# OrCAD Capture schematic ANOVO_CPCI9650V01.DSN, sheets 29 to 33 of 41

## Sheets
29 -J4 USB &SATA &AUDIO &COM: size C; title: 29--J4 HDD&LVDS&AUDIO
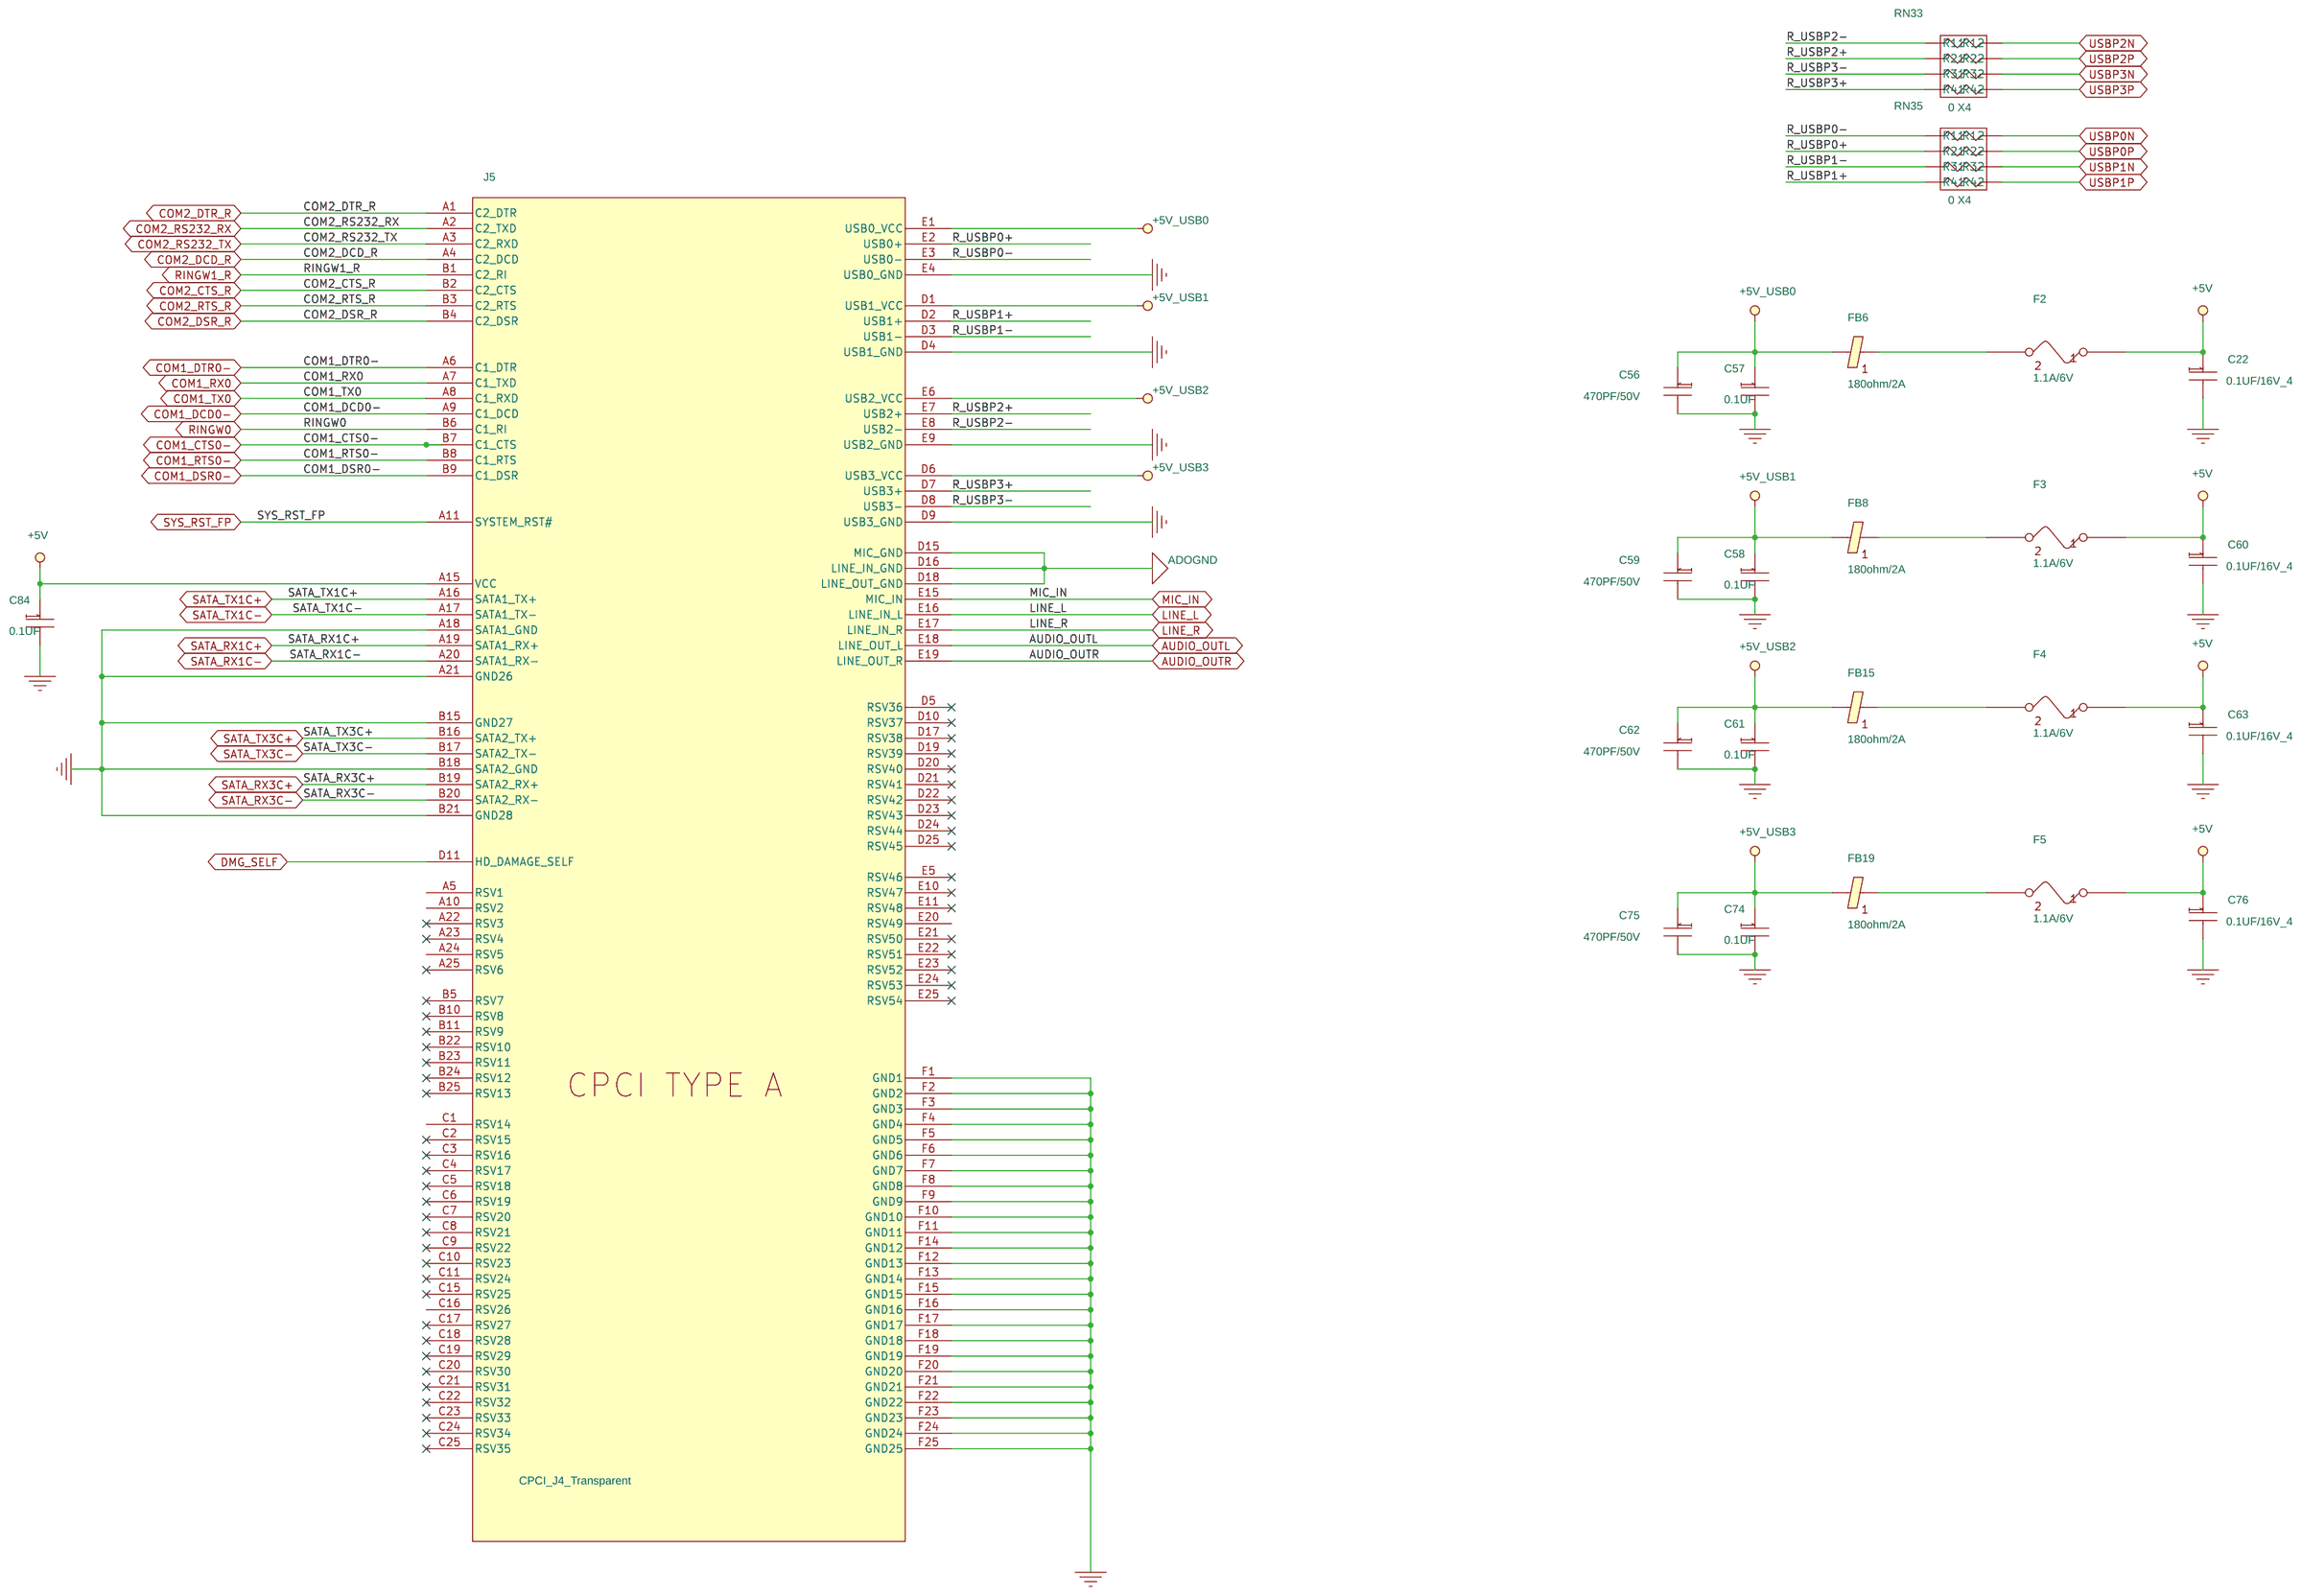
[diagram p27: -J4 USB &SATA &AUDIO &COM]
30 -J5 VGA &DVI &LVDS: size C; title: 30--J5 VGA&USB&ETC
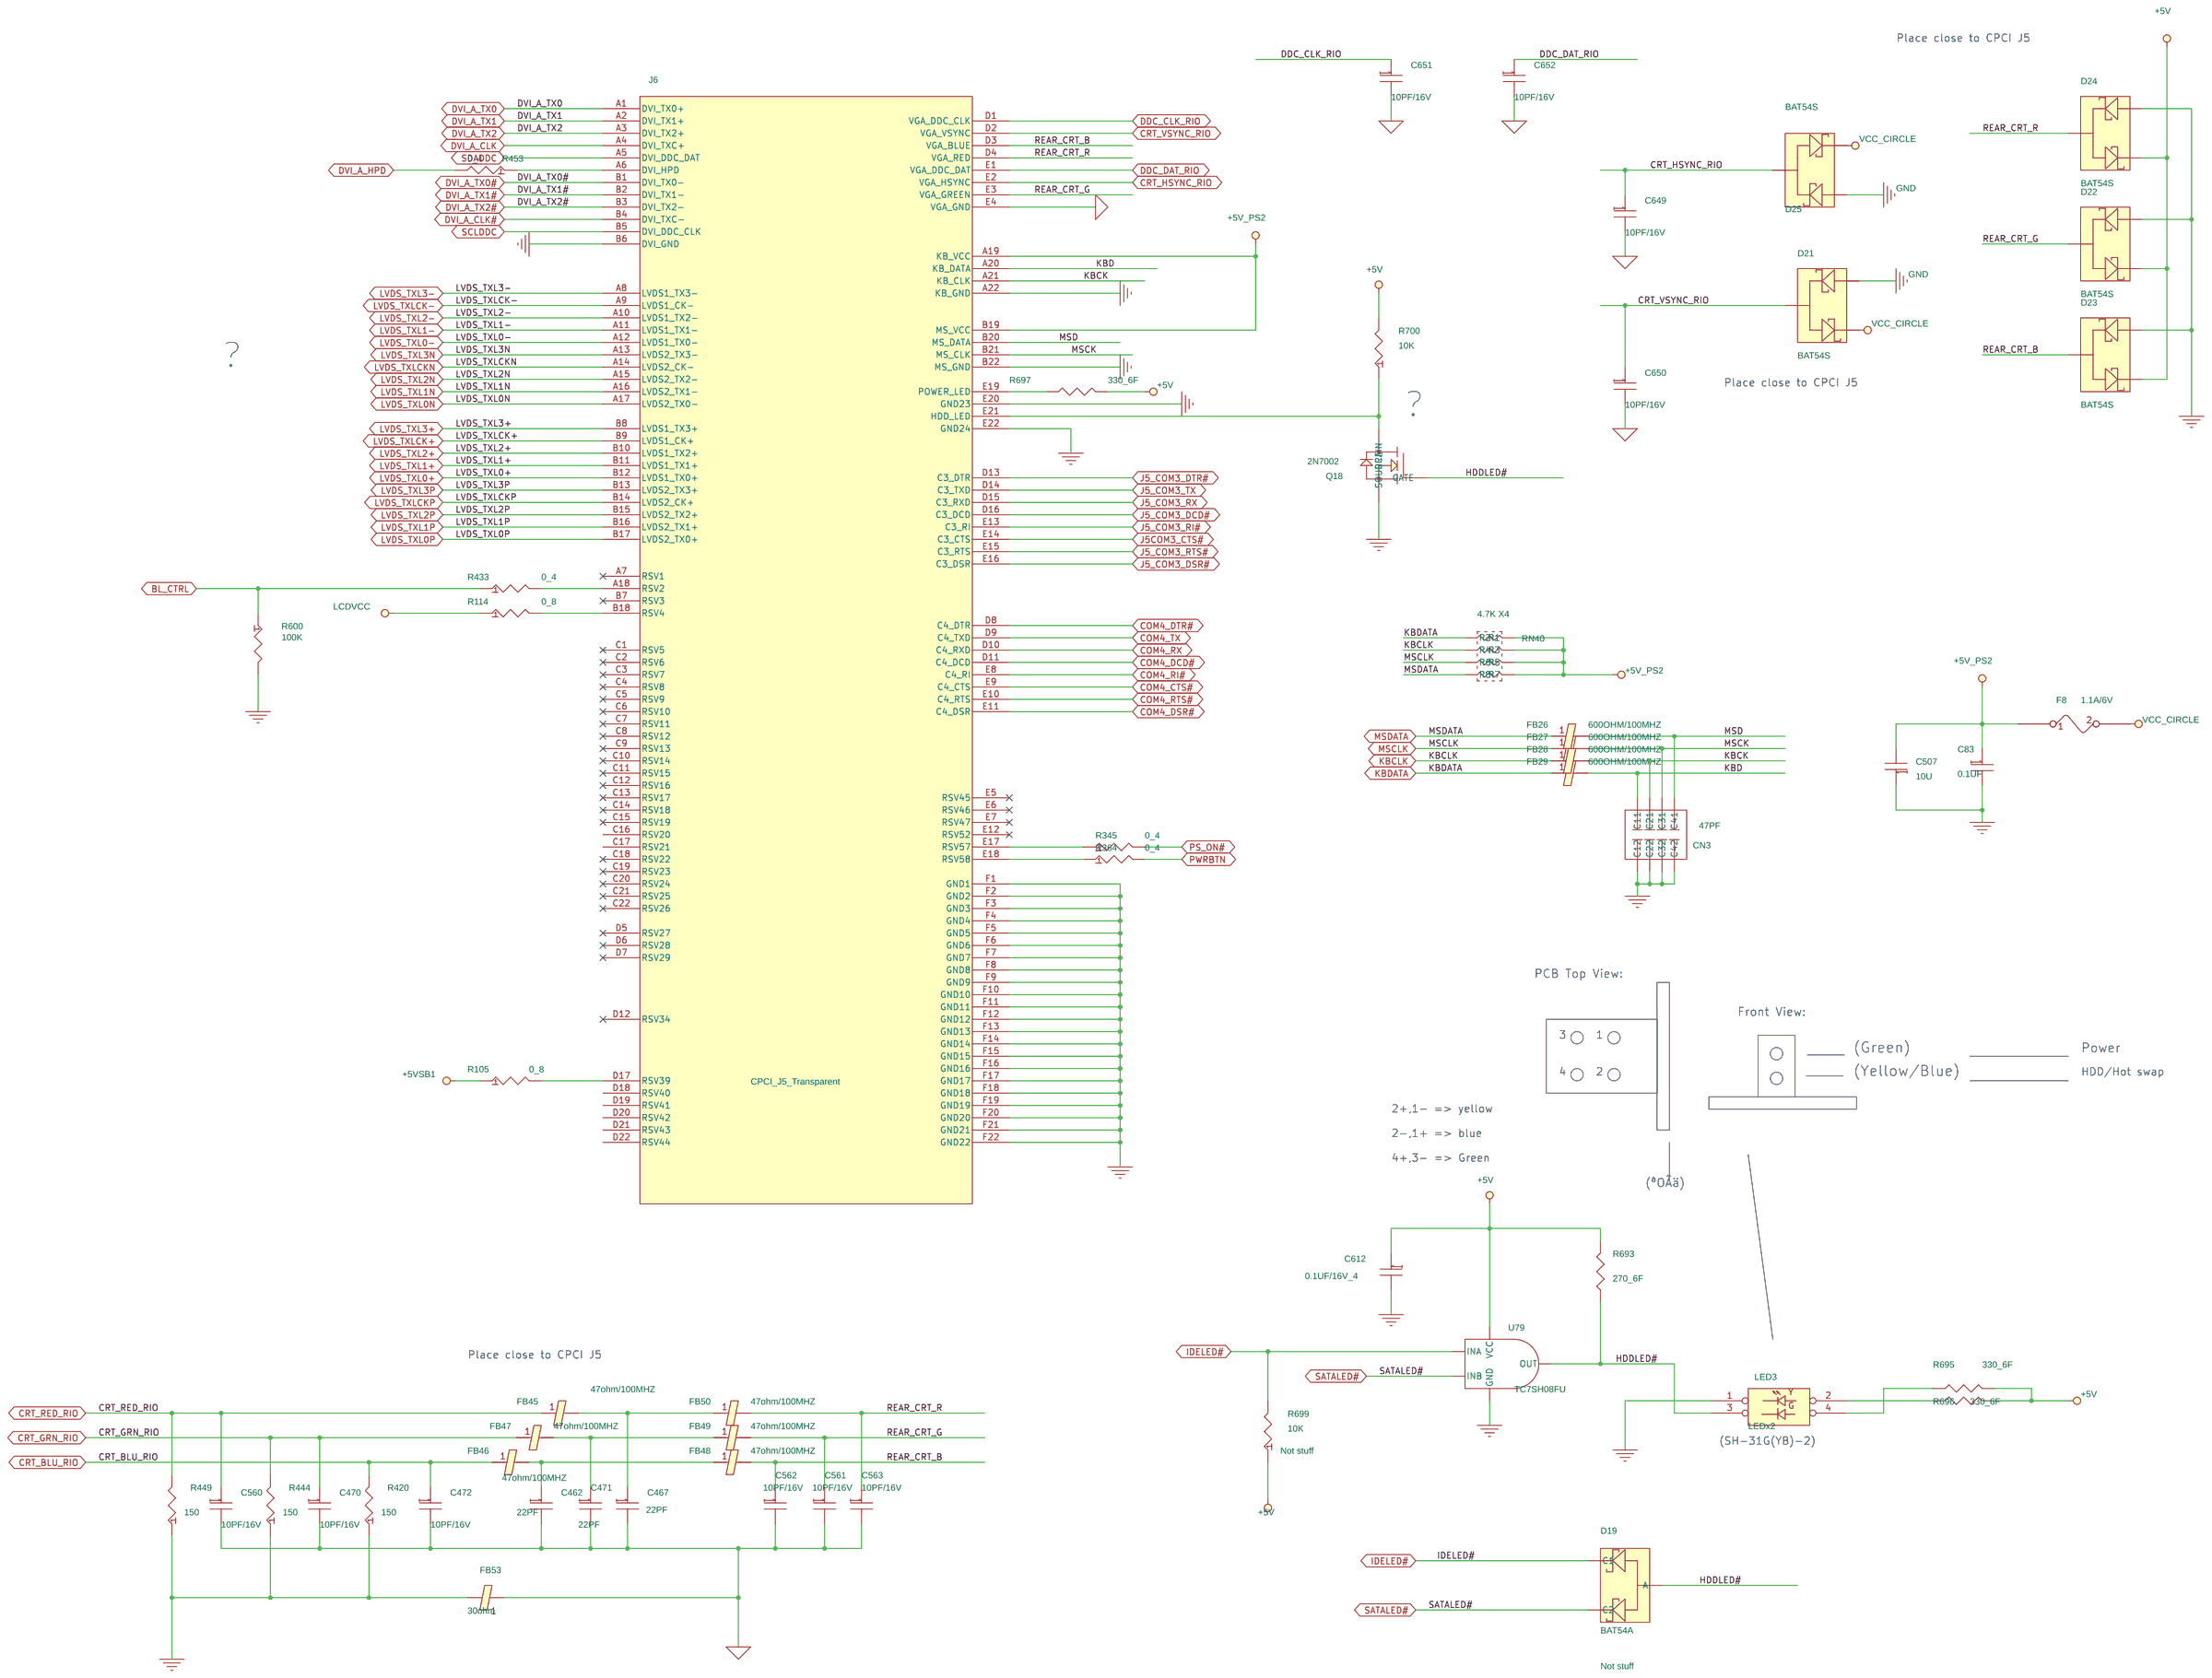
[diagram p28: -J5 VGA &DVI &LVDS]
31 -VCORE: size C; title: 31--POWER-ISL6262(VCORE)
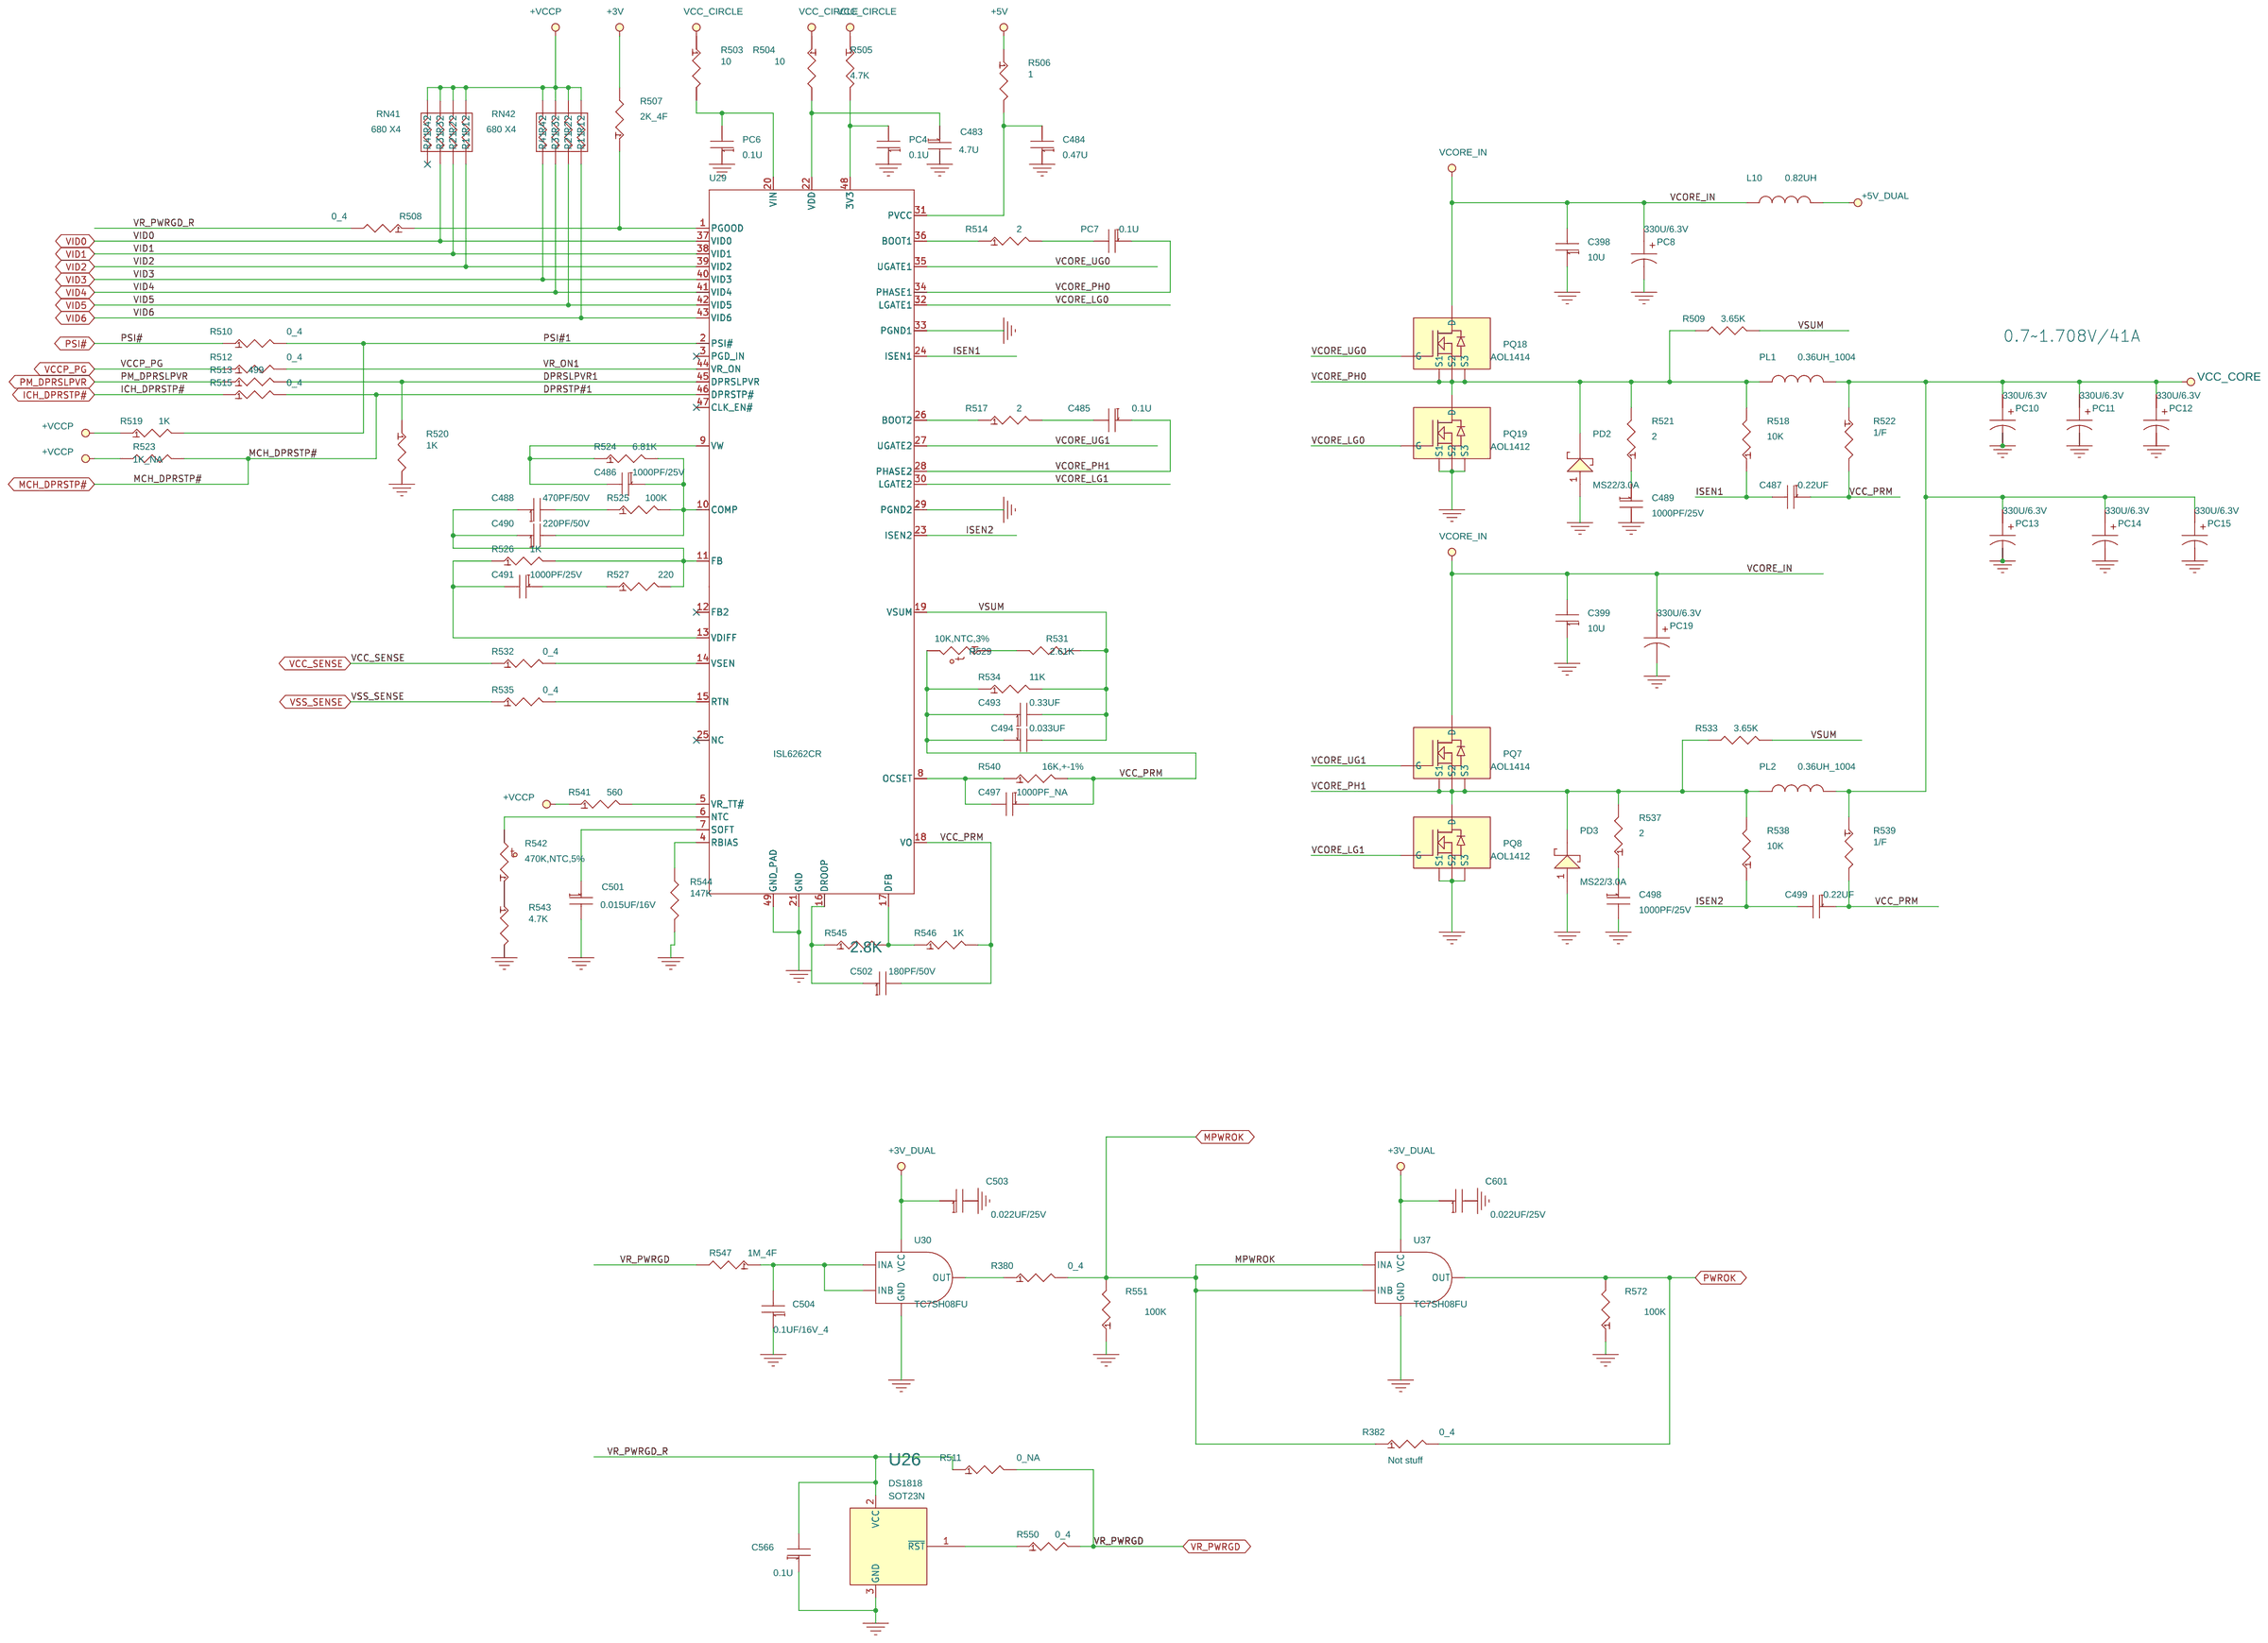
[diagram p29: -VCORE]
32 -1.05V & 1.25V: size C; title: 32--ISL6227(MCH&ICH)
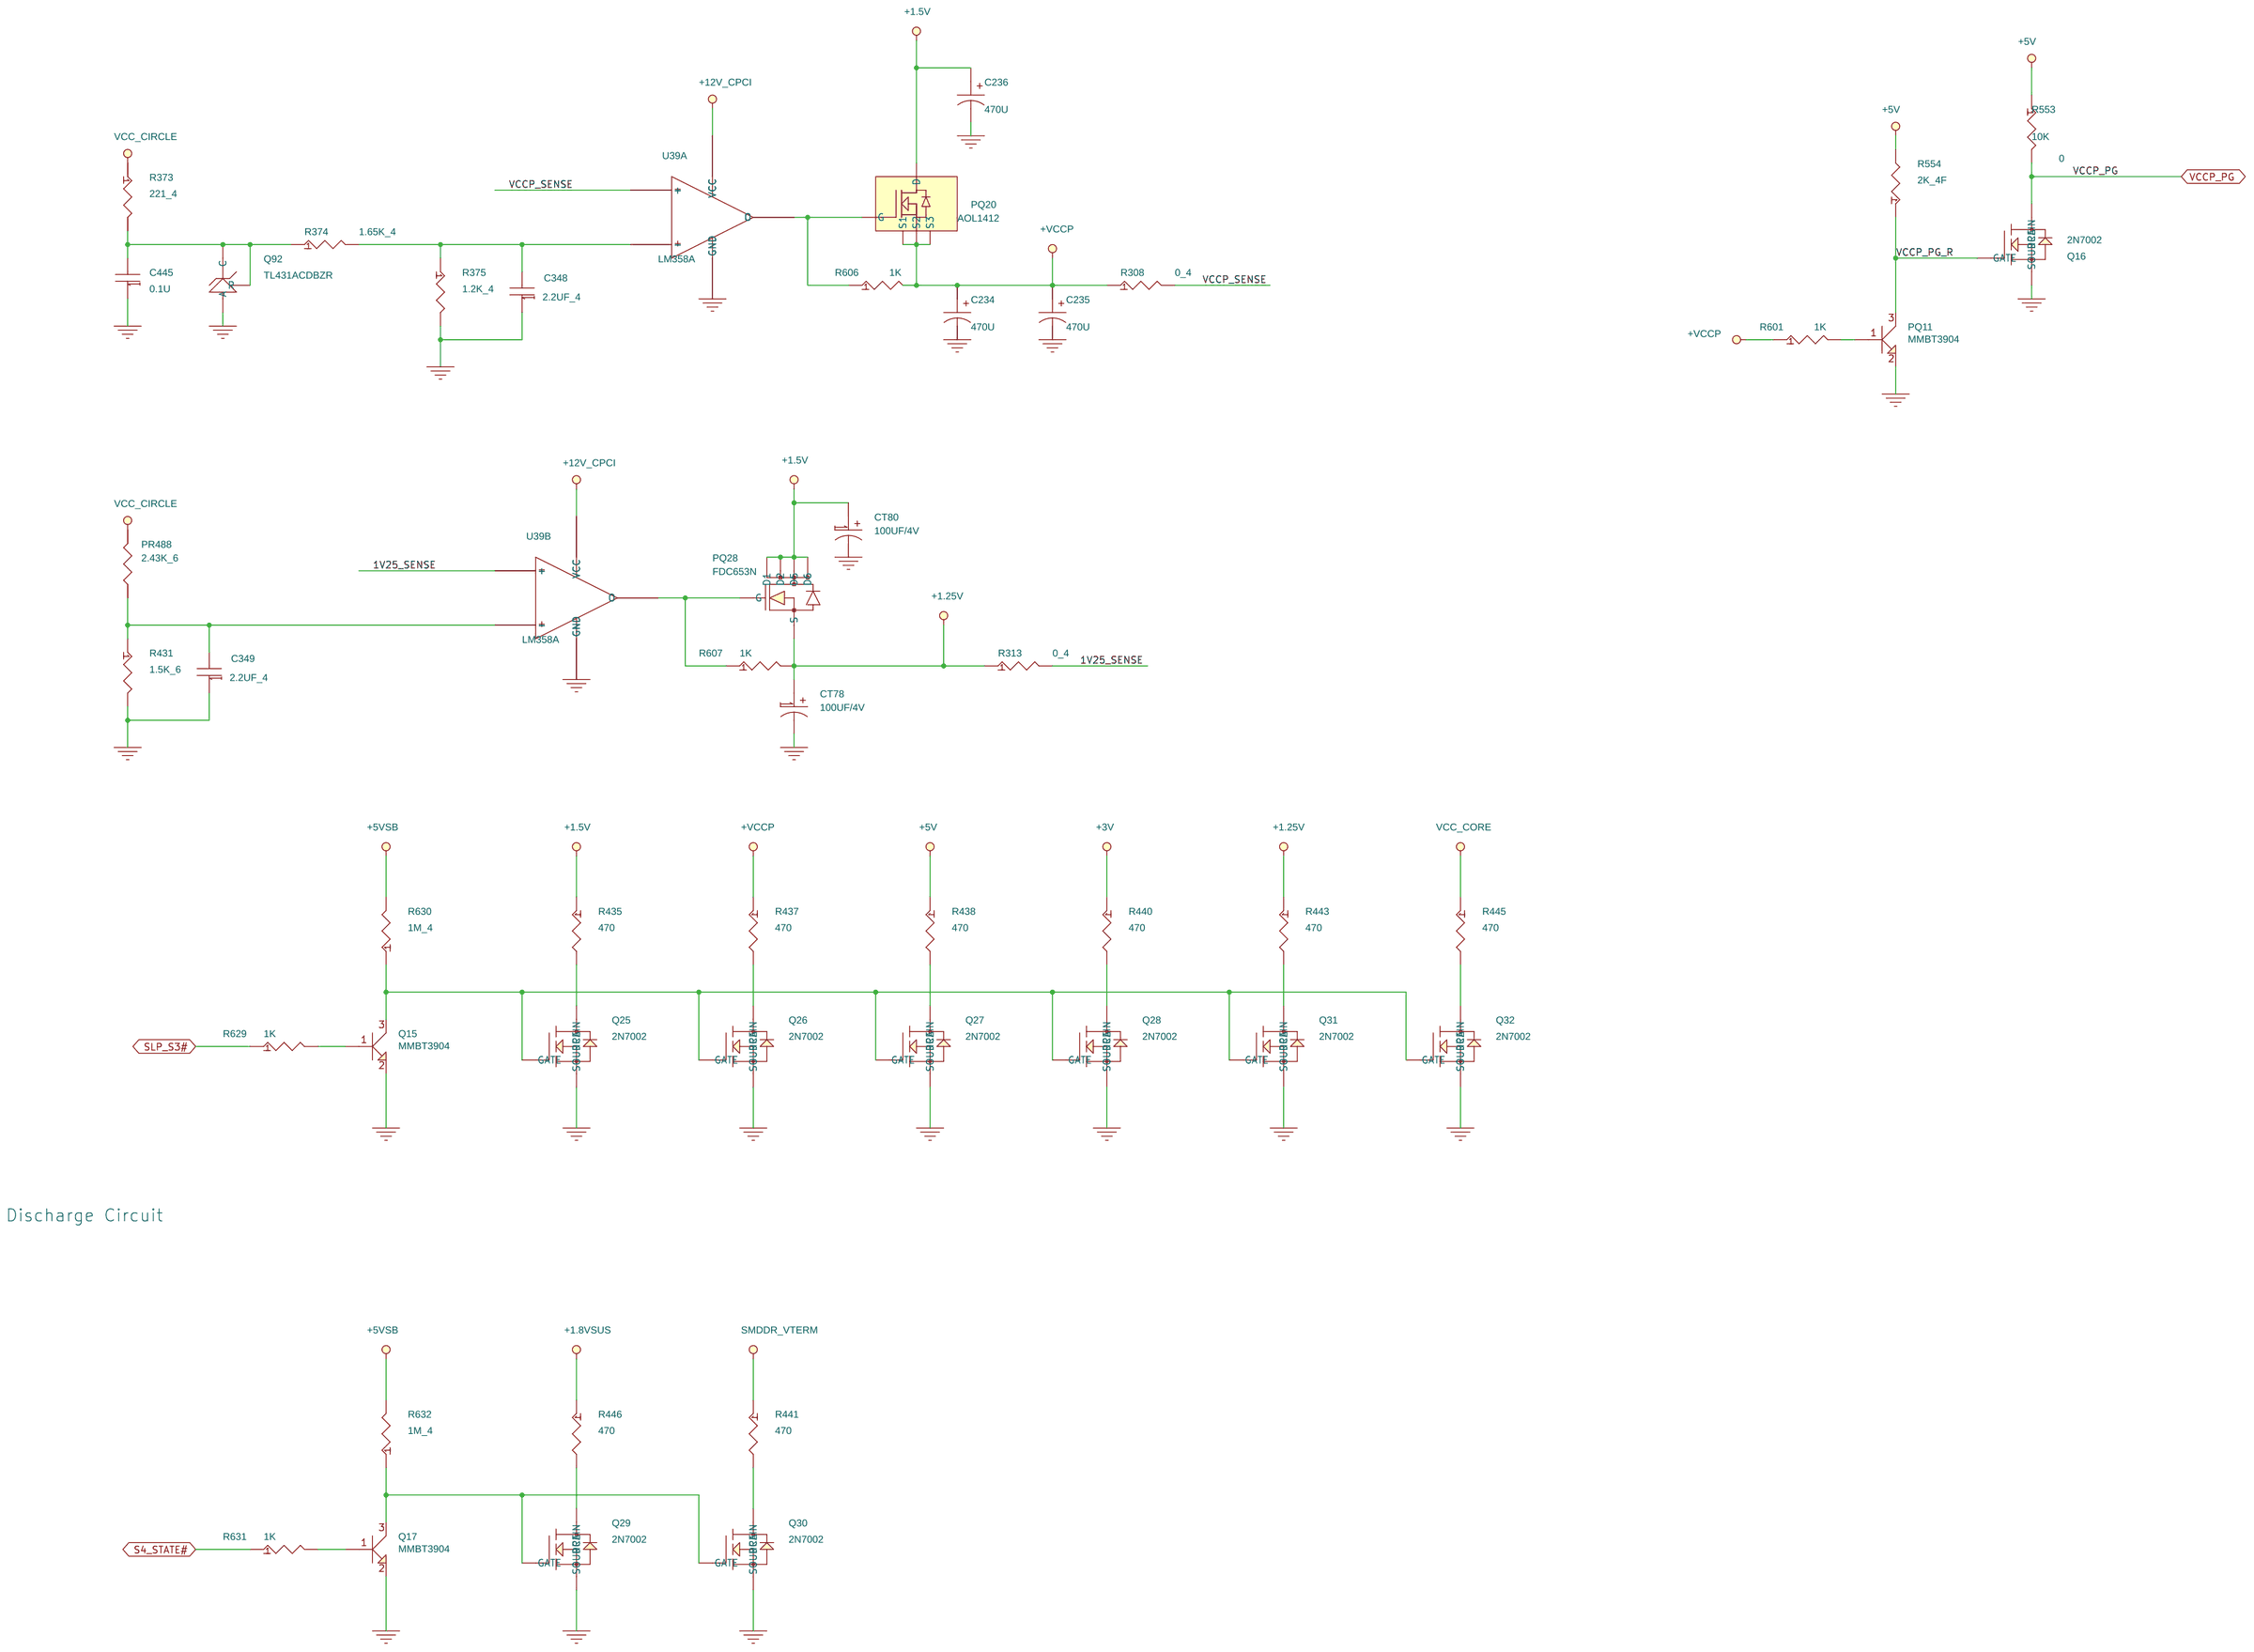
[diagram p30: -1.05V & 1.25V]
33 -1.8V & 1.5V: size C; title: 33--1.8VSUS/0.9VTERM(TPS51116)
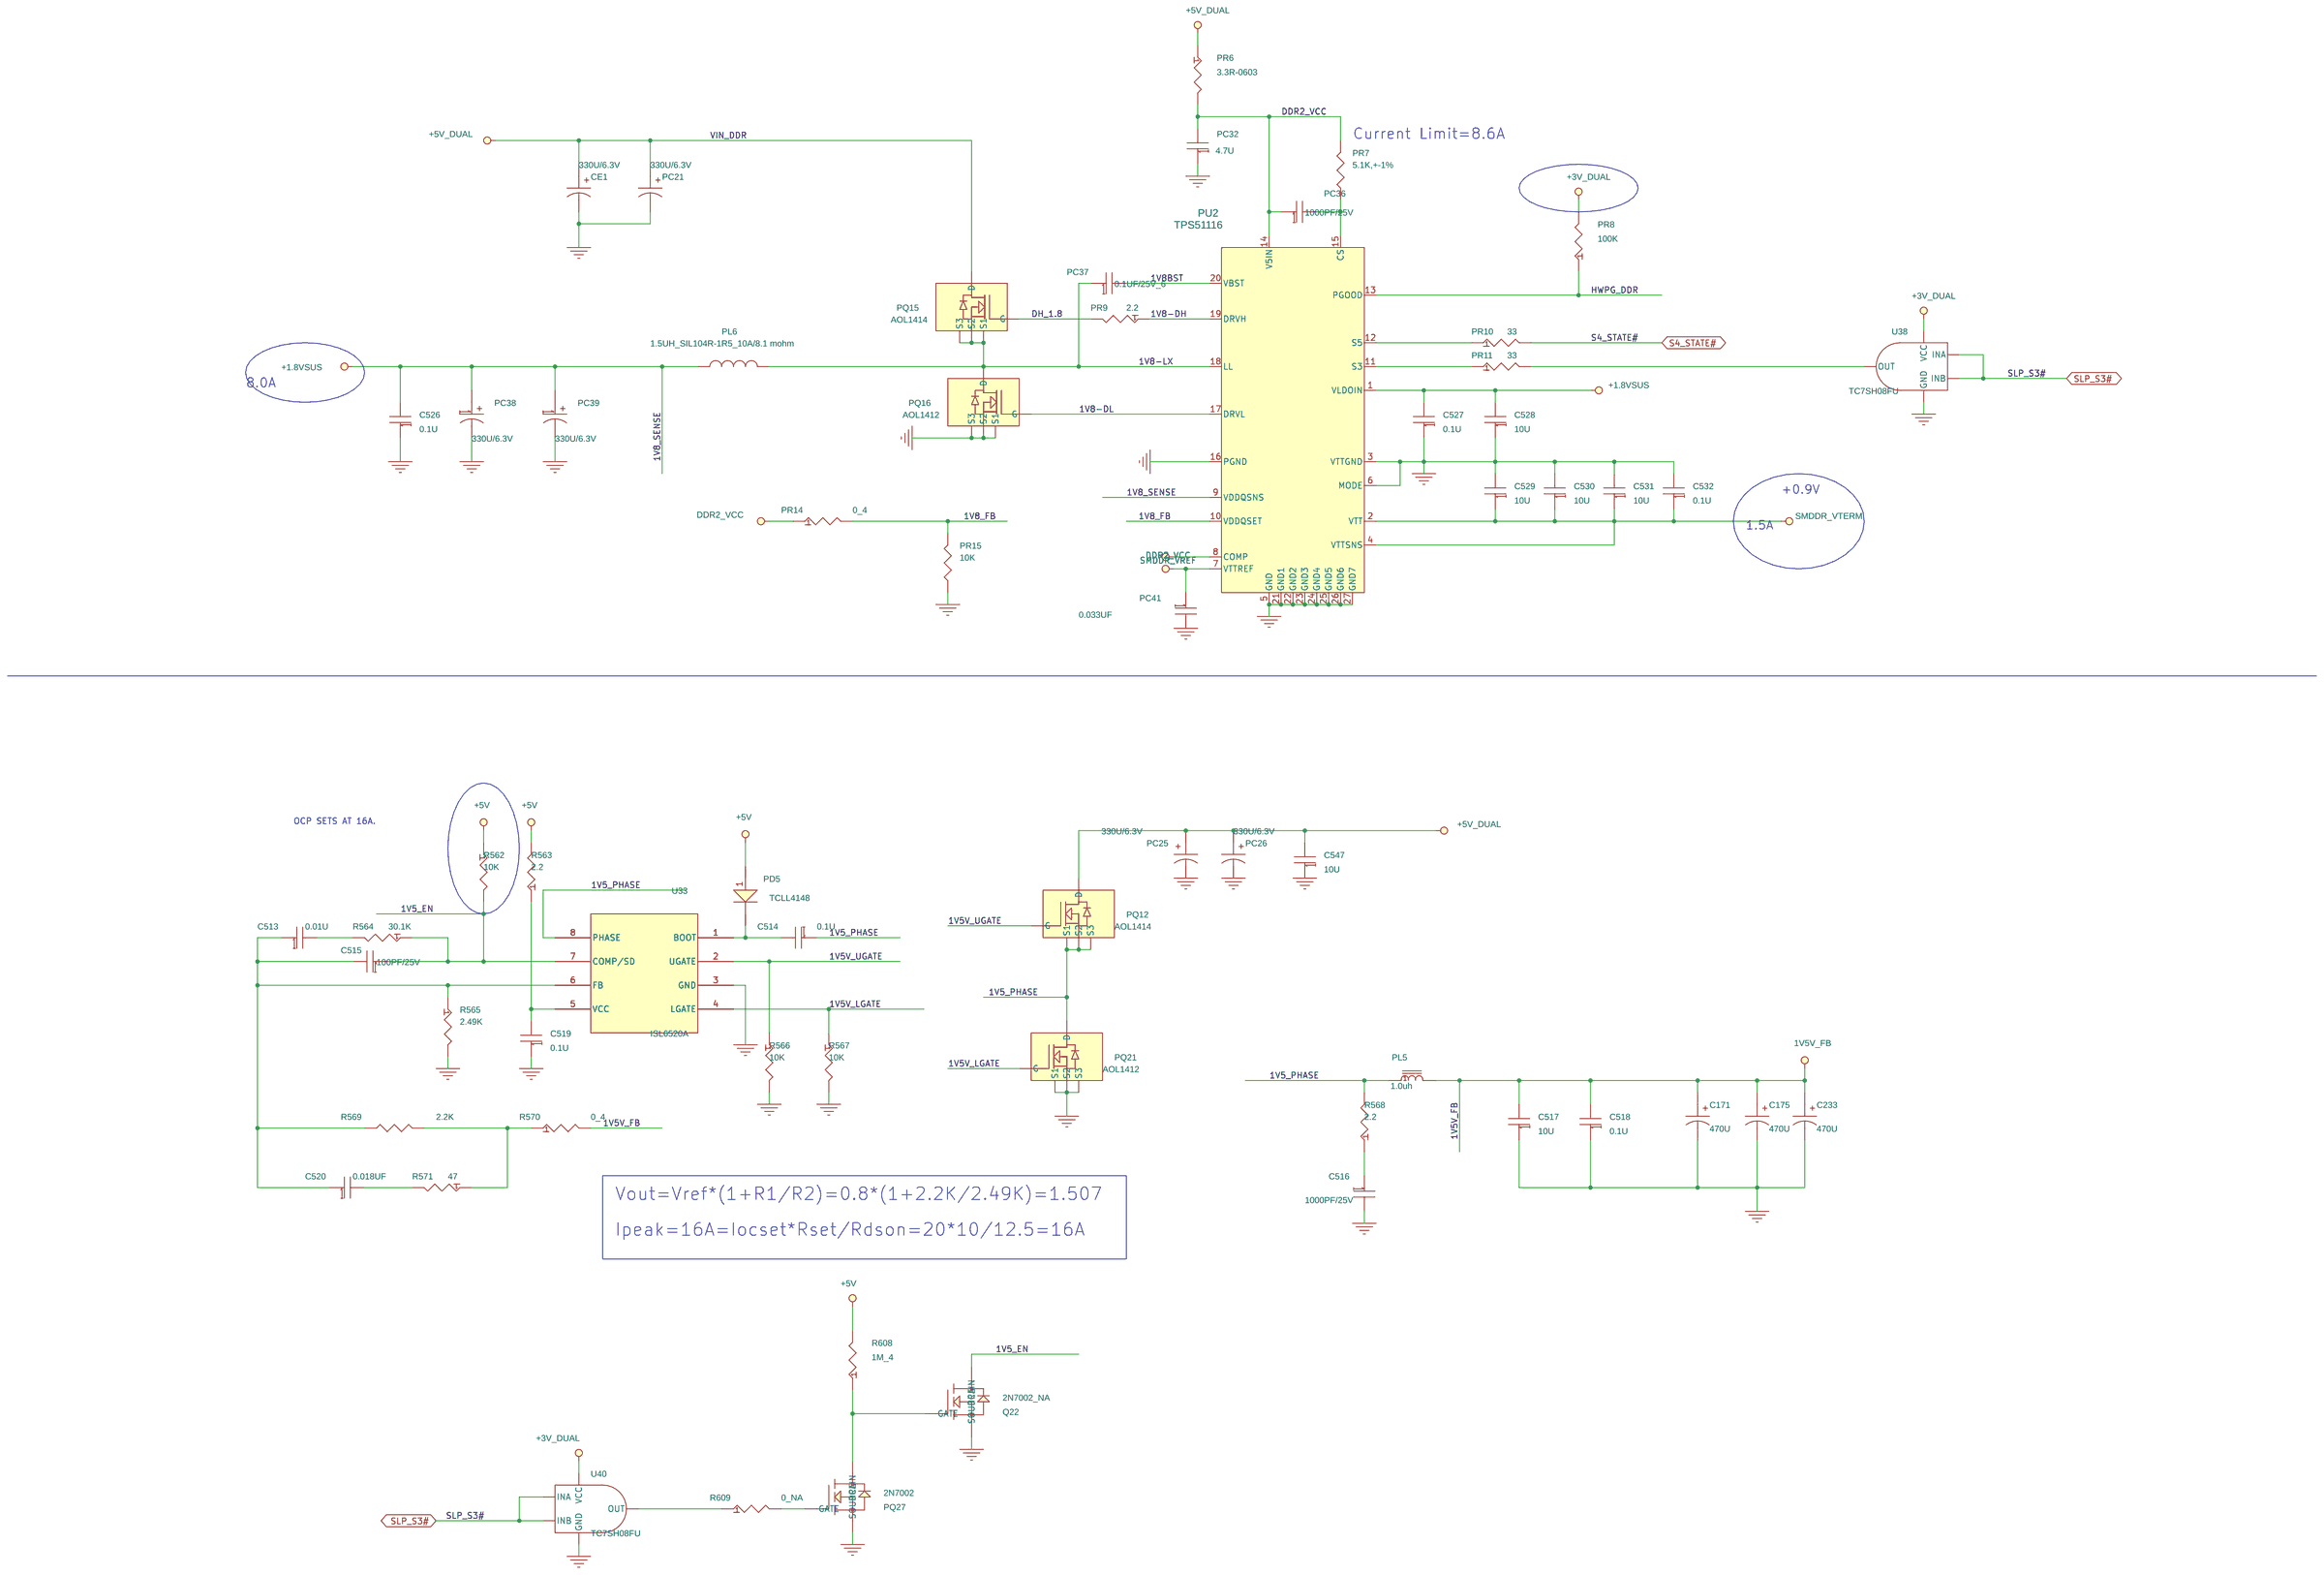
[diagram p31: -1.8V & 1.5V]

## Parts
sheet -1.05V & 1.25V
C234  470U  [1812A]
C235  470U  [1812A]
C236  470U  [1812A]
C348  2.2UF_4  [0402D]
C349  2.2UF_4  [0402D]
C445  0.1U  [0402D]
CT78  100UF/4V  [C3530]
CT80  100UF/4V  [C3530]
PQ11  MMBT3904  [SOT23N_5]
PQ20  AOL1412  [SO_8FL_5P_OA]
PQ28  FDC653N  [SSOT6-2_8-95]
PR488  2.43K_6  [0603D]
Q15  MMBT3904  [SOT23N_5]
Q16  2N7002  [SOT23N_5]
Q17  MMBT3904  [SOT23N_5]
Q25  2N7002  [SOT23N_5]
Q26  2N7002  [SOT23N_5]
Q27  2N7002  [SOT23N_5]
Q28  2N7002  [SOT23N_5]
Q29  2N7002  [SOT23N_5]
Q30  2N7002  [SOT23N_5]
Q31  2N7002  [SOT23N_5]
Q32  2N7002  [SOT23N_5]
Q92  TL431ACDBZR  [SOT23N]
R308  0_4  [0402D]
R313  0_4  [0402D]
R373  221_4  [0402D]
R374  1.65K_4  [0402D]
R375  1.2K_4  [0402D]
R431  1.5K_6  [0402D]
R435  470  [0402D]
R437  470  [0402D]
R438  470  [0402D]
R440  470  [0402D]
R441  470  [0402D]
R443  470  [0402D]
R445  470  [0402D]
R446  470  [0402D]
R553  10K  [0402D]
R554  2K_4F  [0402D]
R601  1K  [0402D]
R606  1K  [0402D]
R607  1K  [0402D]
R629  1K  [0402D]
R630  1M_4  [0402D]
R631  1K  [0402D]
R632  1M_4  [0402D]
U39  LM358A  [SO8]  (sections A,B)
sheet -1.8V & 1.5V
C171  470U  [1812A]
C175  470U  [1812A]
C233  470U  [1812A]
C513  0.01U  [0402D]
C514  0.1U  [0402D]
C515  100PF/25V  [0603D]
C516  1000PF/25V  [0603D]
C517  10U  [0805D]
C518  0.1U  [0402D]
C519  0.1U  [0402D]
C520  0.018UF  [0603D]
C526  0.1U  [0402D]
C527  0.1U  [0402D]
C528  10U  [0805D]
C529  10U  [0805D]
C530  10U  [0805D]
C531  10U  [0805D]
C532  0.1U  [0402D]
C547  10U  [0805D]
CE1  330U/6.3V  [1812A]
PC21  330U/6.3V  [1812A]
PC25  330U/6.3V  [1812A]
PC26  330U/6.3V  [1812A]
PC32  4.7U  [0805D]
PC36  1000PF/25V  [0603D]
PC37  0.1UF/25V_6  [0603D]
PC38  330U/6.3V  [1812A]
PC39  330U/6.3V  [1812A]
PC41  0.033UF  [0603D]
PD5  TCLL4148  [DC1506N]
PL5  1.0uh  [smpi1004]
PL6  1.5UH_SIL104R-1R5_10A/8.1 mohm  [CDRH104R]
PQ12  AOL1414  [SO_8FL_5P_OA]
PQ15  AOL1414  [SO_8FL_5P_OA]
PQ16  AOL1412  [SO_8FL_5P_OA]
PQ21  AOL1412  [SO_8FL_5P_OA]
PQ27  2N7002  [SOT23N_5]
PR6  3.3R-0603  [0603D]
PR7  5.1K,+-1%  [0402D]
PR8  100K  [0402D]
PR9  2.2  [0805D]
PR10  33  [0402D]
PR11  33  [0402D]
PR14  0_4  [0402D]
PR15  10K  [0402D]
PU2  TPS51116  [TSSOP20-6_4-65-27P]
Q22  2N7002_NA  [SOT23N_5]
R562  10K  [0402D]
R563  2.2  [0805D]
R564  30.1K  [0603D]
R565  2.49K  [0603D]
R566  10K  [0402D]
R567  10K  [0402D]
R568  2.2  [0805D]
R569  2.2K  [0603D]
R570  0_4  [0402D]
R571  47  [0603D]
R608  1M_4  [0402D]
R609  0_NA  [0402D]
U33  ISL6520A  [SO8]
U38  TC7SH08FU  [SSOP5_TOSHIBA]
U40  TC7SH08FU  [SSOP5_TOSHIBA]
sheet -J4 USB &SATA &AUDIO &COM
C22  0.1UF/16V_4  [0402D]
C56  470PF/50V  [0402D]
C57  0.1UF  [0402D]
C58  0.1UF  [0402D]
C59  470PF/50V  [0402D]
C60  0.1UF/16V_4  [0402D]
C61  0.1UF  [0402D]
C62  470PF/50V  [0402D]
C63  0.1UF/16V_4  [0402D]
C74  0.1UF  [0402D]
C75  470PF/50V  [0402D]
C76  0.1UF/16V_4  [0402D]
C84  0.1UF  [0402D]
F2  1.1A/6V  [POLYSW_MINISMDC110]
F3  1.1A/6V  [POLYSW_MINISMDC110]
F4  1.1A/6V  [POLYSW_MINISMDC110]
F5  1.1A/6V  [POLYSW_MINISMDC110]
FB6  180ohm/2A  [0805D]
FB8  180ohm/2A  [0805D]
FB15  180ohm/2A  [0805D]
FB19  180ohm/2A  [0805D]
J5  CPCI_J4_Transparent  [conn_cpci25x5_p13]
RN33  0 X4  [RP_8P4R_0804B]
RN35  0 X4  [RP_8P4R_0804B]
sheet -J5 VGA &DVI &LVDS
C83  0.1UF  [0402D]
C462  22PF  [0402D]
C467  22PF  [0402D]
C470  10PF/16V  [0402D]
C471  22PF  [0402D]
C472  10PF/16V  [0402D]
C507  10U  [0805D]
C560  10PF/16V  [0402D]
C561  10PF/16V  [0402D]
C562  10PF/16V  [0402D]
C563  10PF/16V  [0402D]
C612  0.1UF/16V_4  [0402D]
C649  10PF/16V  [0402D]
C650  10PF/16V  [0402D]
C651  10PF/16V  [0402D]
C652  10PF/16V  [0402D]
CN3  47PF  [RPSOA_8D]
D19  BAT54A  [SOT23N_5]
D21  BAT54S  [SOT23N_5]
D22  BAT54S  [SOT23N_5]
D23  BAT54S  [SOT23N_5]
D24  BAT54S  [SOT23N_5]
D25  BAT54S  [SOT23N_5]
F8  1.1A/6V  [POLYSW_MINISMDC110]
FB26  600OHM/100MHZ  [0603D]
FB27  600OHM/100MHZ  [0603D]
FB28  600OHM/100MHZ  [0603D]
FB29  600OHM/100MHZ  [0603D]
FB45  47ohm/100MHZ  [0603D]
FB46  47ohm/100MHZ  [0603D]
FB47  47ohm/100MHZ  [0603D]
FB48  47ohm/100MHZ  [0603D]
FB49  47ohm/100MHZ  [0603D]
FB50  47ohm/100MHZ  [0603D]
FB53  30ohm  [0805D]
J6  CPCI_J5_Transparent  [conn_cpci22x5_p11]
LED3  LEDx2  [LED_2x2D]
Q18  2N7002  [SOT23N_5]
R105  0_8  [0805D]
R114  0_8  [0805D]
R345  0_4  [0402D]
R364  0_4  [0402D]
R420  150  [0402D]
R433  0_4  [0402D]
R444  150  [0402D]
R449  150  [0402D]
R453  0_4  [0402D]
R600  100K  [0402D]
R693  270_6F  [0603D]
R695  330_6F  [0603D]
R696  330_6F  [0603D]
R697  330_6F  [0603D]
R699  10K  [0402D]
R700  10K  [0402D]
RN40  4.7K X4  [RPSOA_8C]
U79  TC7SH08FU  [SSOP5_TOSHIBA]
sheet -VCORE
C398  10U  [0805D]
C399  10U  [0805D]
C483  4.7U  [0805D]
C484  0.47U  [0603D]
C485  0.1U  [0402D]
C486  1000PF/25V  [0603D]
C487  0.22UF  [0603D]
C488  470PF/50V  [0402D]
C489  1000PF/25V  [0603D]
C490  220PF/50V  [0402D]
C491  1000PF/25V  [0603D]
C493  0.33UF  [0402D]
C494  0.033UF  [0603D]
C497  1000PF_NA  [0603D]
C498  1000PF/25V  [0603D]
C499  0.22UF  [0603D]
C501  0.015UF/16V  [0603D]
C502  180PF/50V  [0603D]
C503  0.022UF/25V  [0402D]
C504  0.1UF/16V_4  [0402D]
C566  0.1U  [0402D]
C601  0.022UF/25V  [0402D]
L10  0.82UH  [SMPI0603]
PC4  0.1U  [0402D]
PC6  0.1U  [0402D]
PC7  0.1U  [0402D]
PC8  330U/6.3V  [1812A]
PC10  330U/6.3V  [1812A]
PC11  330U/6.3V  [1812A]
PC12  330U/6.3V  [1812A]
PC13  330U/6.3V  [1812A]
PC14  330U/6.3V  [1812A]
PC15  330U/6.3V  [1812A]
PC19  330U/6.3V  [1812A]
PD2  MS22/3.0A  [DC2013N]
PD3  MS22/3.0A  [DC2013N]
PL1  0.36UH_1004  [smpi1004]
PL2  0.36UH_1004  [smpi1004]
PQ7  AOL1414  [SO_8FL_5P_OA]
PQ8  AOL1412  [SO_8FL_5P_OA]
PQ18  AOL1414  [SO_8FL_5P_OA]
PQ19  AOL1412  [SO_8FL_5P_OA]
R380  0_4  [0402D]
R382  0_4  [0402D]
R503  10  [0603D]
R504  10  [0603D]
R505  4.7K  [0402D]
R506  1  [0603D]
R507  2K_4F  [0402D]
R508  0_4  [0402D]
R509  3.65K  [0603D]
R510  0_4  [0402D]
R511  0_NA  [0402D]
R512  0_4  [0402D]
R513  499  [0603D]
R514  2  [0603D]
R515  0_4  [0402D]
R517  2  [0603D]
R518  10K  [0402D]
R519  1K  [0402D]
R520  1K  [0402D]
R521  2  [0603D]
R522  1/F  [0402D]
R523  1K_NA  [0402D]
R524  6.81K  [0603D]
R525  100K  [0402D]
R526  1K  [0402D]
R527  220  [0402D]
R529  10K,NTC,3%  [0603D]
R531  2.61K  [0603D]
R532  0_4  [0402D]
R533  3.65K  [0603D]
R534  11K  [0603D]
R535  0_4  [0402D]
R537  2  [0603D]
R538  10K  [0402D]
R539  1/F  [0402D]
R540  16K,+-1%  [0603D]
R541  560  [0402D]
R542  470K,NTC,5%  [0402D]
R543  4.7K  [0402D]
R544  147K  [0603D]
R545  2.8K  [0603D]
R546  1K  [0402D]
R547  1M_4F  [0402D]
R550  0_4  [0402D]
R551  100K  [0402D]
R572  100K  [0402D]
RN41  680 X4  [RP_8P4R_0804B]
RN42  680 X4  [RP_8P4R_0804B]
U26  DS1818  [SOT23N]
U29  ISL6262CR  [hvqfn48]
U30  TC7SH08FU  [SSOP5_TOSHIBA]
U37  TC7SH08FU  [SSOP5_TOSHIBA]

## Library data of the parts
C171 C175 C233-C236 = CAPACITOR_POL: 2ND PART FIELD: CH7470LM8L1; ANOVO DESCRIPTION: TANCap,470U,6.3V,20%,D size, SMT; ANOVO PART NUMBER: 272634771011; Function Code: CLG; NOTE: ok; Part Number: CH7470LM8L1
C348 C349 = CAP_NP: ANOVO DESCRIPTION: CAP;2.2U ,6.3V ,10% ,0402 ,X7R ,SMT; ANOVO PART NUMBER: 272041225201
C445 C485 C514 C518 C519 C526 C527 C532 PC4 PC6 PC7 = CAP_NP: ANOVO DESCRIPTION: CAP;0.1U ,16V ,10% ,0402 ,X7R ,SMT; ANOVO PART NUMBER: 272043104201; Part Type: CCAP
CT78 CT80 = CAP_T: ANOVO DESCRIPTION: TANCAP;100U ,4V,+-20%,C3530,SMT; ANOVO PART NUMBER: 272631070011; Part Type: TAN CAP
PQ11 Q15 Q17 = NPN: ANOVO DESCRIPTION: TRANS;MMBT3904,NPN,40V,200mA,SOT23; ANOVO PART NUMBER: 288203904001; BACKSIDE: 0; Part Type: TRANSISTOR; SMT: YES; Datasheet: \\Rdserver\norcocis\datasheet\transistor\fairchild\MMBT3904.pdf
PQ8 PQ16 PQ19-PQ21 = MOS-N_0: ANOVO DESCRIPTION: TRANS;AOL1412,N-MOSFET,3.9MOHM,30V,85A,SO-8,Alpha & Omega Semiconductor; ANOVO PART NUMBER: 288221412001
PQ28 = SI3442DV_0: TRANSISTOR MOSFET FDC653N(30V,4.8A); 2ND PART FIELD: BAM653N0Z03; 8ND PART FIELD: TOP; ANOVO DESCRIPTION: TRANS,FDC653N,NPN,30V,4.8A,SSOT6,SMT; ANOVO PART NUMBER: 288200653001; COST NT$: 0; COST US$: 0; Dell Function Code: PWR.Support; Function Code: DCD; LAYER: TOP; Part Number: BAM653N0Z03; Quanta Function Code: DCD
PR488 = R: anovo description: RES;2.43K ,1/10W ,1% ,0603 ,SMT; anovo part number: 271071243111
PQ27 Q16 Q18 Q22 Q25-Q32 = MOSFET_N_3P: ANOVO DESCRIPTION: TRANS;2N7002,N-MOSFET,60V,500mA,SOT23; ANOVO PART NUMBER: 288227002001; BACKSIDE: 0; Part Type: MOSFET; SMT: YES
Q92 = IC-TL431ACDBZR_SOT-23: ANOVO DESCRIPTION: IC;TL431CSK,1%,2.5V,ADJ REG,SOT23; ANOVO PART NUMBER: 286400431001
R308 R313 R345 R364 R433 = R_v2: ANOVO DESCRIPTION: RES;0 ,1/16W ,5% ,0402 ,SMT; ANOVO PART NUMBER: 271040000301; ID: 42; Part Type: RESISTOR; SMT: YES
R373 = R_v2: ANOVO DESCRIPTION: RES;221 ,1/16W ,1% ,0402 ,SMT; ANOVO PART NUMBER: 271040221011; Part Type: RESISTOR; SMT: YES
R374 = R_v2: ANOVO DESCRIPTION: RES;1.65K ,1/16W ,1% ,0402 ,SMT; ANOVO PART NUMBER: 271040165111; Part Type: RESISTOR; SMT: YES
R375 = R_v2: ANOVO DESCRIPTION: RES;1.2K ,1/16W ,1% ,0402 ,SMT; ANOVO PART NUMBER: 271040122101; Part Type: RESISTOR
R431 = R_v2: ANOVO DESCRIPTION: RES;1.5K ,1/10W ,1% ,0603 ,SMT; ANOVO PART NUMBER: 271071152101; Part Type: RESISTOR; SMT: YES
R435 R437 R438 R440 R441 R443 R445 R446 = R_v2: ANOVO DESCRIPTION: RES;470 ,1/16W ,5% ,0402 ,SMT; ANOVO PART NUMBER: 271040471301; POWER: 1/16w; Part Type: RESISTOR
R518 R538 R553 R700 = R_v2: ANOVO DESCRIPTION: RES;10K ,1/16W ,5% ,0402 ,SMT; ANOVO PART NUMBER: 271040103301; BACKSIDE: 0; Part Type: RESISTOR; SMT: YES
R507 R554 = R_v2: ANOVO DESCRIPTION: RES;2K ,1/16W ,5% ,0402 ,SMT; ANOVO PART NUMBER: 271040202301; Part Type: RESISTOR
R519 R520 R526 R546 R601 R606 R607 R629 R631 = R_v2: ANOVO DESCRIPTION: RES;1K ,1/16W ,1% ,0402 ,SMT; ANOVO PART NUMBER: 271040102101; Part Type: RESISTOR
R608 R630 R632 = R_v2: ANOVO DESCRIPTION: RES;1M ,1/16W ,5% ,0402 ,SMT; ANOVO PART NUMBER: 271040105301; BACKSIDE: 0; Part Type: RESISTOR; SMT: YES
U39 = LM358A
C513 = CAP_NP: ANOVO DESCRIPTION: CAP;0.01U ,16V ,10% ,0402 ,X7R ,SMT; ANOVO PART NUMBER: 272043103201; Part Type: CCAP
C515 = CAP_NP: ANOVO DESCRIPTION: CAP;100P ,50V ,5% ,0603 ,NPO ,SMT; ANOVO PART NUMBER: 272075101101; BACKSIDE: 0; Part Type: CCAP; SMT: YES
C486 C489 C491 C497 C498 C516 PC36 = CAP_NP: ANOVO DESCRIPTION: CAP;1000P ,50V ,10% ,0603 ,X7R ,SMT; ANOVO PART NUMBER: 272075102201; BACKSIDE: 0; Part Type: CCAP; SMT: YES
C398 C399 C507 C517 C528-C531 C547 = CAP_NP: ANOVO DESCRIPTION: CAP;10U,10V,+80-20%,0805,Y5V,SMT; ANOVO PART NUMBER: 272002106401; Part Type: CCAP
C520 = CAP_NP: ANOVO DESCRIPTION: CAP;0.018U ,50V ,10% ,0603 ,X7R ,SMT; ANOVO PART NUMBER: 272075183201; BACKSIDE: 0; Part Type: CCAP; SMT: YES
CE1 PC8 PC10-PC15 PC19 PC21 PC25 PC26 = CAPACITOR_POL: ANOVO DESCRIPTION: TANCAP,330U,6.3V,20%,D size, SMT; ANOVO PART NUMBER: 272633371011
C483 PC32 = CAP_NP: ANOVO DESCRIPTION: CAP;4.7U ,10V ,+80-20% ,0805 ,Y5V ,SMT; ANOVO PART NUMBER: 272002475401; Part Type: CCAP
PC37 = CAP_NP: ANOVO DESCRIPTION: CAP;0.1U ,25V ,10% ,0603 ,X7R ,SMT; ANOVO PART NUMBER: 272074104201; BACKSIDE: 0; Part Type: CCAP; SMT: YES
PC38 PC39 = CAP_T: ANOVO DESCRIPTION: TANCAP,330U,6.3V,20%,D size, SMT; ANOVO PART NUMBER: 272633371011
C494 PC41 = CAP_NP: ANOVO DESCRIPTION: CAP;0.033U ,50V ,10% ,0603 ,X7R ,SMT; ANOVO PART NUMBER: 272075333201; BACKSIDE: 0; Part Type: CCAP; SMT: YES
PD5 = DIODE: ANOVO DESCRIPTION: DIODE;TCLL4148,100V,150MA,3.5*1.5MM,SMT; ANOVO PART NUMBER: 288104148001; BACKSIDE: 0; Part Type: FAST; SMT: YES; Datasheet: \\Rdserver\norcocis\datasheet\DIODE\vishay\LS4148.PDF
PL5 = INDUCTOR: SMT: YES; anovo description: CHOKE,1.0UH,20A,1004,SMT; anovo part number: 275001067600
PL6 = INDUCTOR_4: CHOKE COIL 1.5UH30%10A(SIL104R-1R5PF)L-F; 2ND PART FIELD: DC-15A00010; 8ND PART FIELD: BOT; ANOVO DESCRIPTION: Inductor, 1.5uH,10A,10%,1040,SMT; ANOVO PART NUMBER: 275001556500; COST NT$: 3.8; COST US$: 0.1134328; Function Code: DCD; Part Number: DC-15A00010; Part_No: DC-15A00010; Quanta Function Code: DDR
PQ7 PQ12 PQ15 PQ18 = MOS-N_0: ANOVO DESCRIPTION: TRANS;AOL1414,N-MOSFET,3.9MOHM,30V,85A,SO-8,Alpha & Omega Semiconductor; ANOVO PART NUMBER: 288221414001
PR6 = R_v2: RESISTOR CHIP 3.3 1/10W +-5%(0603)L-F; 2ND PART FIELD: CS-3303J910; 8ND PART FIELD: TOP; ANOVO DESCRIPTION: RES,3.3,1/10W,5%,0603,SMT; ANOVO PART NUMBER: 271071033831; COST NT$: 0; COST US$: 0; Dell Function Code: PWR.Plane.Regulator_1p8v0p9v; Function Code: DCD; LAYER: TOP; Part Number: CS-3303J910; Part_No: CS-3303J910; Quanta Function Code: DDR; Subsystem ID: Video.PWR.Regulator
PR7 = R_6: ANOVO DESCRIPTION: RES;5.1K ,1/16W ,5% ,0402 ,SMT; ANOVO PART NUMBER: 271040512301; BACKSIDE: 0; Part Type: RESISTOR
PR8 R525 R551 R572 R600 = R_v2: ANOVO DESCRIPTION: RES;100K ,1/16W ,5% ,0402 ,SMT; ANOVO PART NUMBER: 271040104301; Part Type: RESISTOR
PR9 R563 R568 = R_v2: ANOVO DESCRIPTION: RES;2.2 ,1/8W ,1% ,0805 ,SMT; ANOVO PART NUMBER: 271002022811; BACKCOMP: YES; BACKSIDE: YES; ID: 126; Part Type: RESISTOR; Power: 1/16W; SMT: YES
PR10 PR11 = R_v2: ANOVO DESCRIPTION: RES;33 ,1/16W ,5% ,0402 ,SMT; ANOVO PART NUMBER: 271040330301; POWER: 1/16W; Part Type: RESISTOR
PR14 R380 R453 = R_v2: ANOVO DESCRIPTION: RES;0 ,1/16W ,5% ,0402 ,SMT; ANOVO PART NUMBER: 271040000301; BACKCOMP: YES; BACKSIDE: YES; ID: 0; Part Type: RESISTOR; SMT: YES
PR15 = R_17: ANOVO DESCRIPTION: RES;10K ,1/16W ,1% ,0402 ,SMT; ANOVO PART NUMBER: 271040103101; Part Type: RESISTOR; SMT: YES
PU2 = MAX8550ETI_2: IC(20P) TPS51116PWPRG4(TSSOP)L-F; 2ND PART FIELD: AL051116K13; 8ND PART FIELD: TOP; ANOVO DESCRIPTION: IC,TPS51116PWP,PWM CTRL,1.8V,TSSOP,20P,TI; ANOVO PART NUMBER: 286405111601; COST NT$: 0; COST US$: 0; Function Code: DCD; LAYER: TOP; Part Number: AL051116K13; Part_No: AL051116K13; Quanta Function Code: DDR
R562 R566 R567 = R_v2: ANOVO DESCRIPTION: RES;10K ,1/16W ,1% ,0402 ,SMT; ANOVO PART NUMBER: 271040103101; Part Type: RESISTOR; SMT: YES
R564 = R_v2: RES;30.1K ,1/10W ,1% ,0603 ,SMT; ANOVO DESCRIPTION: RES;30.1K ,1/10W ,1% ,0603 ,SMT; ANOVO PART NUMBER: 271071301211; BACKCOMP: YES; Part Type: RESISTOR; SMT: YES
R565 = R_v2: RES;2.49K ,1/10W ,1% ,0603 ,SMT; ANOVO DESCRIPTION: RES;2.49K ,1/10W ,1% ,0603 ,SMT; ANOVO PART NUMBER: 271071249111; BACKCOMP: YES; Part Type: RESISTOR; SMT: YES
R569 = R_12: ANOVO DESCRIPTION: RES;2.2K ,1/10W ,1% ,0603 ,SMT; ANOVO PART NUMBER: 271071222101; Function Code: ADO; Part Type: RESISTOR
R508 R510-R512 R515 R550 R570 R609 = R_v2: ANOVO DESCRIPTION: RES;0 ,1/16W ,5% ,0402 ,SMT; ANOVO PART NUMBER: 271040000301; BACKCOMP: YES; Part Type: RESISTOR; SMT: YES
R571 = R_v2: RES;47 ,1/10W ,1% ,0603 ,SMT; ANOVO DESCRIPTION: RES;47 ,1/10W ,1% ,0603 ,SMT; ANOVO PART NUMBER: 271071470101; BACKCOMP: YES; Part Type: RESISTOR; SMT: YES
U33 = 286306520012: ANOVO DESCRIPTION: IC;ISL6520ACBZ,BUCK PWM CTLR,SOIC,8P,Intersil; ANOVO PART NUMBER: 286406520001
U30 U37 U38 U40 U79 = TC7SH08FU
C22 C57 C58 C60 C61 C63 C74 C76 C83 C84 C504 C612 = CAP_NP: ANOVO DESCRIPTION: CAP;0.1U ,16V ,+80-20% ,0402 ,Y5V ,SMT; ANOVO PART NUMBER: 272043104401; BACKSIDE: 0; Part Type: CCAP; SMT: YES
C56 C59 C62 C75 = CAP_NP: ANOVO DESCRIPTION: CAP;470P ,50V ,10% ,0402 ,X7R ,SMT; ANOVO PART NUMBER: 272045471201; BACKSIDE: 0; Part Type: CCAP
F2-F5 F8 = FUSE: ANOVO DESCRIPTION: FUSE,1.1A/6V,POLY SWITCH,1812,SMT; ANOVO PART NUMBER: 295000010009; BACKSIDE: 0; ROOM: DVI; SMT: YES
FB6 FB8 FB15 FB19 = FERRITE_BEAD: ANOVO DESCRIPTION: FERRITE CHIP,180 OHM/100MHZ,2A,0805,SMT; ANOVO PART NUMBER: 273000180001; BACKSIDE: 0; Part Type: FERRITE BEAD; ROOM: IDE; SMT: YES
J5 = CPCI_J4_Transparent_18: ANOVO DESCRIPTION: CON;Press Header;femaW/shield;Yellow;110 /123Pins;5ROWS;2.00mm;R/A;CPCI Type A,(J1/J4)5352068-1,TYCO; ANOVO PART NUMBER: 333150110002
RN33 RN35 = R_8P4R: network 0ohmx4 8pin smt +-5%; ANOVO DESCRIPTION: RP;0*4 ,8P ,1/16W ,5% ,0408,SMT; ANOVO PART NUMBER: 271590000301; Part Type: NETWORK; SMT: YES
C462 C467 C471 = CAP_NP: ANOVO DESCRIPTION: CAP;22P ,50V ,5% ,0402 ,NPO ,SMT; ANOVO PART NUMBER: 272045220101; BACKSIDE: 0; Part Type: CCAP; SMT: YES
C470 C472 C560-C563 C649-C652 = CAP_NP: ANOVO DESCRIPTION: CAP;10P ,16V ,5% ,0402 ,NPO ,SMT; ANOVO PART NUMBER: 272043100101; BACKSIDE: 0; Part Type: CCAP; SMT: YES
CN3 = CAP_8P4C: ANOVO DESCRIPTION: CP,47P*4  ,8P,50V ,10%,0612,NPO,SMT; ANOVO PART NUMBER: 272615470201; BACKSIDE: 0; Part Type: NETWORK CAP; SMT: YES
D19 = BAT54A: ANOVO DESCRIPTION: DIODE;BAT54A,SCHOTTKY DIODE,SOT23; ANOVO PART NUMBER: 288100054001; DUMMY: Not stuff
D21-D25 = BAT54S: ANOVO DESCRIPTION: DIODE;BAT54S,SCHOTTKY DIODE,SOT23; ANOVO PART NUMBER: 288100054021; BACKSIDE: 0; Part Type: SCHOTTKY; SMT: YES; Datasheet: \\Rdserver\norcocis\datasheet\DIODE\fairchild\BAT54.pdf
FB26-FB29 = FERRITE_BEAD: ANOVO DESCRIPTION: FERRITE CHIP;600 OHM/100MHZ,0603,350mA,SMT; ANOVO PART NUMBER: 273006012200; Part Type: FERRITE BEAD
FB45-FB50 = FERRITE_BEAD: ANOVO DESCRIPTION: FERRITE CHIP;47 OHM/100MHZ,25%,0603, <0.05 ohm,600mA,SMT; ANOVO PART NUMBER: 273004703200; BACKSIDE: 0; Part Type: FERRITE BEAD; SMT: YES
FB53 = FERRITE_BEAD: ANOVO DESCRIPTION: FERRITE CHIP;30 OHM/100MHZ£¬0805£¬5A£¬SMT; ANOVO PART NUMBER: 273003005300; BACKSIDE: 0; Part Type: FERRITE BEAD; SMT: YES
J6 = CPCI_J5_Transparent_11: ANOVO DESCRIPTION: CON;Press Header;female;W/shield;Yellow;110/121 Pins;5 ROWS;2.00mm;R/A;CPCI Type B,5352152-4,TYCO; ANOVO PART NUMBER: 333150110001
LED3 = KTL_33GY_0
R105 R114 = R_v2: ANOVO DESCRIPTION: RES,0 ,1/8W ,5% ,0805 ,SMT; ANOVO PART NUMBER: 271002000301
R420 R444 R449 = R_v2: ANOVO DESCRIPTION: RES;150,1/16W,1%,0402,SMT; ANOVO PART NUMBER: 271040151101; BACKCOMP: NO; BACKSIDE: 0; Part Type: RESISTOR; SMT: YES
R693 = R_0: ANOVO DESCRIPTION: RES;270 £¬1/10W £¬1% £¬0603 £¬SMT; ANOVO PART NUMBER: 271071271101; BACKSIDE: 0; Part Number: CS12212FB19; Part Type: RESISTOR; Res: 221; SMT: YES; Tolerance: 1%; Watt: 1/16W
R695-R697 = R_0: ANOVO DESCRIPTION: RES;330 £¬1/10W £¬1% £¬0603 £¬SMT; ANOVO PART NUMBER: 271071331101; BACKSIDE: 0; Part Number: CS12212FB19; Part Type: RESISTOR; Res: 221; SMT: YES; Tolerance: 1%; Watt: 1/16W
R699 = R_v2: ANOVO DESCRIPTION: RES;10K ,1/16W ,5% ,0402 ,SMT; ANOVO PART NUMBER: 271040103301; BACKSIDE: 0; DUMMY: Not stuff; Part Type: RESISTOR; SMT: YES
RN40 = 10*4_4: ANOVO DESCRIPTION: RP;4.7K*4 ,8P ,1/16W ,5% ,0612 ,SMT; ANOVO PART NUMBER: 271610472301
C484 = CAP_NP: ANOVO DESCRIPTION: CAP;0.47U ,16V ,20% ,0603 ,X5R ,SMT; ANOVO PART NUMBER: 272073474301; BACKSIDE: 0; Part Type: CCAP; SMT: YES
C487 C499 = CAP_NP: ANOVO DESCRIPTION: CAP;0.22U ,16V ,10% ,0603 ,X7R ,SMT; ANOVO PART NUMBER: 272073224201; BACKSIDE: 0; Part Type: CCAP; SMT: YES
C488 = CAP_NP: ANOVO DESCRIPTION: CAP;470P ,50V ,10% ,0402 ,X7R ,SMT; ANOVO PART NUMBER: 272045471201; Part Type: CCAP
C490 = CAP_NP: ANOVO DESCRIPTION: CAP;220P ,50V ,5% ,0402 ,NPO ,SMT; ANOVO PART NUMBER: 272045221101; Part Type: CCAP
C493 = CAP_NP: ANOVO DESCRIPTION: CAP;0.33U ,10V ,10% ,0402 ,X5R ,SMT; ANOVO PART NUMBER: 272042334201; BACKSIDE: 0; Part Type: CCAP; SMT: YES
C501 = CAP_NP: ANOVO DESCRIPTION: CAP;0.015U ,16V ,10% ,0603 ,X7R ,SMT; ANOVO PART NUMBER: 272073153201; Part Type: CCAP
C502 = CAP_NP: ANOVO DESCRIPTION: CAP;180P ,50V ,5% ,0603 ,NPO ,SMT; ANOVO PART NUMBER: 272075181101; BACKSIDE: 0; Part Type: CCAP; SMT: YES
C503 C601 = CAP_NP: ANOVO DESCRIPTION: CAP;0.022U ,50V ,10% ,0402 ,X7R ,SMT; ANOVO PART NUMBER: 272045223201; BACKSIDE: 0; Part Type: CCAP; SMT: YES
C566 = CAP_NP: ANOVO DESCRIPTION: CAP;0.1U ,16V ,10% ,0402 ,X7R ,SMT; ANOVO PART NUMBER: 272043104201; BACKSIDE: 0; Part Type: CCAP; SMT: YES
L10 = INDUCTOR_3: ANOVO DESCRIPTION: CHOKE; 0.82UH,7MM*7MM,20A,8MOHM,SMT; ANOVO PART NUMBER: 275008247600; Function Code: CLG; Mounted: Y
PD2 PD3 = DIODE_SCHOTTKY: ANOVO DESCRIPTION: DIODE;SSA34,SCHOTTKY,30V,3.0A,DC2013N,VISHAY; ANOVO PART NUMBER: 288100034001; BACKSIDE: 0; Part Type: SCHOTTKY; SMT: YES; Datasheet: \\Rdserver\norcocis\datasheet\DIODE\mospec\MS20-MS22.PDF
PL1 PL2 = INDUCTOR_0: ANOVO DESCRIPTION: Inductor, 0.36uH,28A,10%,1004,SMT; ANOVO PART NUMBER: 275003648600; COST: 9.7; Function Code: CLG; Mounted: Y; Part Number: SMPI 1004HW-R36M
R382 = R_v2: ANOVO DESCRIPTION: RES;0 ,1/16W ,5% ,0402 ,SMT; ANOVO PART NUMBER: 271040000301; BACKCOMP: YES; BACKSIDE: YES; DUMMY: Not stuff; ID: 0; Part Type: RESISTOR; SMT: YES
R503 R504 = R_v2: ANOVO DESCRIPTION: RES;10 ,1/10W ,1% ,0603 ,SMT; ANOVO PART NUMBER: 271071100101; POWER: 1/10W; Part Type: RESISTOR
R505 R543 = R_v2: ANOVO DESCRIPTION: RES;4.7K ,1/16W ,5% ,0402 ,SMT; ANOVO PART NUMBER: 271040472301; Part Type: RESISTOR
R506 = R_v2: ANOVO DESCRIPTION: RES;1 ,1/10W ,5% ,0603 ,SMT; ANOVO PART NUMBER: 271071010301; POWER: 1/10W; Part Type: RESISTOR
R509 R533 = RES;3.65K,1_10W,1%,0603: ANOVO DESCRIPTION: RES;3.65K ,1/10W ,1% ,0603 ,SMT
R513 = R_v2: RES;499,1/10W,1%,0603,SMT; ANOVO DESCRIPTION: RES;499,1/10W,1%,0603,SMT; ANOVO PART NUMBER: 271071499011; BACKCOMP: YES; Part Type: RESISTOR; SMT: YES
R514 R517 R521 R537 = R_v2: ANOVO DESCRIPTION: RES,2   ,1/10W,1% ,0603,SMT; ANOVO PART NUMBER: 271071020101; BACKCOMP: YES; BACKSIDE: YES; ID: 126; Part Type: RESISTOR; Power: 1/16W; SMT: YES
R522 R539 = R_v2: ANOVO DESCRIPTION: RES;1,1/16W,1%,0402,SMT; ANOVO PART NUMBER: 271040010101
R523 = R_0: ANOVO DESCRIPTION: RES;1K ,1/16W ,1% ,0402 ,SMT; ANOVO PART NUMBER: 271040102101; Part Type: RESISTOR
R524 = R_v2: ANOVO DESCRIPTION: RES;6.81K ,1/10W ,1% ,0603 ,SMT; ANOVO PART NUMBER: 271071681111; POWER: 1/10W; Part Type: RESISTOR
R527 = R_v2: ANOVO DESCRIPTION: RES;220 ,1/16W ,5% ,0402 ,SMT; ANOVO PART NUMBER: 271040221301; POWER: 1/16W; Part Type: RESISTOR
R529 = R_THERMISTOR: ANOVO DESCRIPTION: THERMISTOR;10K;1%;RA;0603,SMT; ANOVO PART NUMBER: 271811103100; BACKSIDE: 0; Part Type: THERMISTOR; SMT: YES
R531 = R_0: ANOVO DESCRIPTION: RES;2.61K ,1/10W ,1% ,0603 ,SMT; ANOVO PART NUMBER: 271071261111; FPLIST: RC0603; Part Description: RES;2.61K ,1/10W ,1% ,0603 ,SMT; Part Type: CHIP; Res: 3.65K; Size: 0603; Tolerance: 1%; Watt: 1/10W
R532 R535 = R_v2: ANOVO DESCRIPTION: RES;0 ,1/16W ,5% ,0402 ,SMT; ANOVO PART NUMBER: 271040000301; POWER: 1/16W; Part Type: RESISTOR
R534 = R_v2: ANOVO DESCRIPTION: RES;11K ,1/10W ,1% ,0603 ,SMT; ANOVO PART NUMBER: 271071113101; BACKSIDE: 0; Part Type: RESISTOR; SMT: YES
R540 = R_v2: ANOVO DESCRIPTION: RES;16K  ,1/10W,1% ,0603,SMT; ANOVO PART NUMBER: 271071163101; POWER: 1/10W; Part Type: RESISTOR
R541 = R_v2: ANOVO DESCRIPTION: RES;560 ,1/16W ,5% ,0402 ,SMT; ANOVO PART NUMBER: 271040561301; POWER: 1/16W; Part Type: RESISTOR
R542 = R_THERMISTOR: ANOVO DESCRIPTION: THERMISTOR,470K,NTC,5%,0402,SMT; ANOVO PART NUMBER: 271810474300; BACKSIDE: 0; Part Type: THERMISTOR; SMT: YES
R544 = RES;147K,1_10W_,1%_,0603: ANOVO DESCRIPTION: RES;147K ,1/10W ,1% ,0603 ,SMT
R545 = R_v2: ANOVO DESCRIPTION: RES;2.8K ,1/10W ,1% ,0603 ,SMT; ANOVO PART NUMBER: 271071282101; POWER: 1/10W; Part Type: RESISTOR
R547 = R_v2: ANOVO DESCRIPTION: RES;1M £¬1/16W £¬5% £¬0402 £¬SMT; ANOVO PART NUMBER: 271040105301; Part Type: RESISTOR
RN41 RN42 = R_8P4R: NETWORK 680 OHMX4 8PIN 0402 SMT; ANOVO DESCRIPTION: RP;680*4 ,8P ,1/16W ,5% ,0408,SMT; ANOVO PART NUMBER: 271590681301; BACKCOMP: NO; BACKSIDE: NO; Distributor: CHENXIAO; ID: 459; Part Number: 271590681301; Part Type: NETWORK; SMT: YES
U26 = DS1813_0: ANOVO DESCRIPTION: IC;DS1818,RST CHIP FOR 150MS,3P,SOT23; ANOVO PART NUMBER: 282071818001
U29 = IC;ISL6262CR,PWM_CTL,QFN48

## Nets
1V5_EN: C515.1 Q22.3(DRAIN) R562.2 R564.1 U33.7(COMP/SD)
1V5_PHASE: C514.1 PL5.1 PQ12.1(S1) PQ12.2(S2) PQ12.3(S3) PQ21.5(D) R568.2 U33.8(PHASE)
1V5V_LGATE: PQ21.4(G) R567.1 U33.4(LGATE)
1V5V_UGATE: PQ12.4(G) R566.1 U33.2(UGATE)
1V8-DH: PR9.1 PU2.19(DRVH)
1V8-DL: PQ16.4(G) PU2.17(DRVL)
1V8-LX: PC37.1 PL6.2 PQ15.1(S1) PQ15.2(S2) PQ15.3(S3) PQ16.5(D) PU2.18(LL)
1V8_FB: PR14.2 PR15.2 PU2.10(VDDQSET)
1V8BST: PC37.2 PU2.20(VBST)
1V25_SENSE: R313.2 U39.6(+)
+1.5V: C171.1 C175.1 C233.1 C236.1 C517.2 C518.2 CT80.1 PL5.2 PQ20.5(D) PQ28.1(D1) PQ28.2(D2) PQ28.5(D5) PQ28.6(D6) R435.1 R570.2 ; also on sheet 6 12 16 18
+1.8VSUS: C526.2 C527.2 C528.2 PC38.1 PC39.1 PL6.1 PU2.1(VLDOIN) PU2.9(VDDQSNS) R446.1 ; also on sheet 9 11 12 14 21 38 39
+1.25V: CT78.1 PQ28.4(S) R313.1 R443.1 R607.2 ; also on sheet 9 12 18 21
+3V: PR488.2 R373.1 R440.1 R505.1 R507.2 ; also on sheet 4 9 10 12 15 16 17 18 19 20 21 22 23 24 25 26 27 28 34 35 41
+3V_DUAL: C503.1 C601.1 PR8.2 U30.5(VCC) U37.5(VCC) U38.5(VCC) U40.5(VCC) ; also on sheet 14 15 16 17 18 19 20 21 26 34 38 40 41
+5V: C22.1 C60.1 C63.1 C76.1 C84.1 C612.1 D21.2 D22.2 D23.2 D24.2 D25.2 F2.1 F3.1 F4.1 F5.1 J5.A15(VCC) PD5.1(A) R438.1 R503.1 R504.1 R506.1 R553.1 R554.2 R562.1 R563.2 R608.2 R693.2 R695.2 R696.2 R697.2 R699.1 R700.2 U79.5(VCC) ; also on sheet 18 21 22 23 24 25 26 27 34 35 40
+5V_DUAL: C547.2 CE1.1 F8.2 L10.2 PC21.1 PC25.1 PC26.1 PQ12.5(D) PQ15.5(D) PR6.1 ; also on sheet 18 21 25 27 34
+5V_PS2: C83.1 C507.2 F8.1 J6.A19(KB_VCC) J6.B19(MS_VCC) RN40.1(R1) RN40.2(R3) RN40.3(R5) RN40.4(R7)
+5V_USB0: C56.1 C57.1 FB6.2 J5.E1(USB0_VCC)
+5V_USB1: C58.1 C59.1 FB8.2 J5.D1(USB1_VCC)
+5V_USB2: C61.1 C62.1 FB15.2 J5.E6(USB2_VCC)
+5V_USB3: C74.1 C75.1 FB19.2 J5.D6(USB3_VCC)
+5VSB: R630.2 R632.2 ; also on sheet 34 36
+5VSB1: R105.1 ; also on sheet 34
+12V_CPCI: U39.8(VCC) ; also on sheet 21 24 25 26 27 34
+VCCP: C234.1 C235.1 PQ20.1(S1) PQ20.2(S2) PQ20.3(S3) R308.1 R437.1 R519.1 R523.2 R541.1 R601.1 R606.2 RN41.2(R12) RN41.4(R22) RN41.6(R32) RN41.8(R42) RN42.2(R12) RN42.4(R22) RN42.6(R32) RN42.8(R42) ; also on sheet 5 6 7 10 11 12 15 18 21
GND: C22.2 C56.2 C57.2 C58.2 C59.2 C60.2 C61.2 C62.2 C63.2 C74.2 C75.2 C76.2 C83.2 C84.2 C171.2 C175.2 C233.2 C234.2 C235.2 C236.2 C348.1 C349.1 C398.1 C399.1 C445.1 C483.2 C484.1 C489.2 C498.2 C501.2 C503.2 C504.1 C507.1 C516.2 C517.1 C518.1 C519.1 C526.1 C527.1 C528.1 C529.2 C530.2 C531.2 C532.2 C547.1 C566.1 C601.2 C612.2 CE1.2 CN3.2(C12) CN3.4(C22) CN3.6(C32) CN3.8(C42) CT78.2 CT80.2 D21.1 D22.1 D23.1 D24.1 D25.1 FB53.2 J5.A18(SATA1_GND) J5.A21(GND26) J5.B15(GND27) J5.B18(SATA2_GND) J5.B21(GND28) J5.D4(USB1_GND) J5.D9(USB3_GND) J5.E4(USB0_GND) J5.E9(USB2_GND) J5.F1(GND1) J5.F2(GND2) J6.A22(KB_GND) J6.B6(DVI_GND) J6.B22(MS_GND) J6.E20(GND23) J6.E22(GND24) J6.F1(GND1) J6.F2(GND2) J6.F3(GND3) J6.F4(GND4) J6.F5(GND5) J6.F6(GND6) J6.F7(GND7) J6.F8(GND8) J6.F9(GND9) J6.F10(GND10) J6.F11(GND11) J6.F12(GND12) J6.F13(GND13) J6.F14(GND14) J6.F15(GND15) J6.F16(GND16) J6.F17(GND17) J6.F18(GND18) J6.F19(GND19) J6.F20(GND20) J6.F21(GND21) J6.F22(GND22) LED3.1 PC4.1 PC6.1 PC8.2 PC10.2 PC11.2 PC12.2 PC13.2 PC14.2 PC15.2 PC19.2 PC21.2 PC25.2 PC26.2 PC32.1 PC38.2 PC39.2 PC41.2 PD2.1(A) PD3.1(A) PQ8.1(S1) PQ8.2(S2) PQ8.3(S3) PQ11.2(E) PQ16.1(S1) PQ16.2(S2) PQ16.3(S3) PQ19.1(S1) PQ19.2(S2) PQ19.3(S3) PQ21.1(S1) PQ21.2(S2) PQ21.3(S3) PQ27.2(SOURCE) PR15.1 PU2.3(VTTGND) PU2.5(GND) PU2.6(MODE) PU2.16(PGND) PU2.21(GND1) PU2.22(GND2) PU2.23(GND3) PU2.24(GND4) PU2.25(GND5) PU2.26(GND6) PU2.27(GND7) Q15.2(E) Q16.2(SOURCE) Q17.2(E) Q18.2(SOURCE) Q22.2(SOURCE) Q25.2(SOURCE) Q26.2(SOURCE) Q27.2(SOURCE) Q28.2(SOURCE) Q29.2(SOURCE) Q30.2(SOURCE) Q31.2(SOURCE) Q32.2(SOURCE) Q92.3(A) R375.2 R420.1 R431.2 R444.1 R449.1 R520.2 R543.2 R544.2 R551.1 R565.2 R566.2 R567.2 R572.1 R600.2 U26.3(GND) U29.21(GND) U29.29(PGND2) U29.33(PGND1) U29.49(GND_PAD) U30.3(GND) U33.3(GND) U37.3(GND) U38.3(GND) U39.4(GND) U40.3(GND) U79.3(GND) ; also on sheet 4 5 6 7 9 10 11 12 13 14 15 16 17 18 19 20 21 22 23 24 25 26 27 28 34 35 36 37 38 39 40 41
GND_VGA: C462.2 C467.2 C470.2 C471.2 C472.2 C560.2 C561.2 C562.2 C563.2 C649.2 C650.2 C651.2 C652.2 FB53.1 J6.E4(VGA_GND)
VCC_CORE: PC10.1 PC11.1 PC12.1 PC13.1 PC14.1 PC15.1 PL1.2 PL2.2 R445.1 R522.1 R539.1 ; also on sheet 6 21
VCC_PRM: C487.1 C493.1 C494.1 C497.1 C499.1 C502.2 R522.2 R529.2 R534.1 R539.2 R540.2 R546.2 U29.18(VO)
VCC_SENSE: R532.1 ; also on sheet 6
VCCP_PG: Q16.3(DRAIN) R512.1 R553.2
VCCP_PG_R: PQ11.3(C) Q16.1(GATE) R554.1
VCCP_SENSE: R308.2 U39.2(+)
VSS_SENSE: R535.1 ; also on sheet 6
ADOGND: J5.D15(MIC_GND) J5.D16(LINE_IN_GND) J5.D18(LINE_OUT_GND) ; also on sheet 23
AUDIO_OUTL: J5.E18(LINE_OUT_L) ; also on sheet 23
AUDIO_OUTR: J5.E19(LINE_OUT_R) ; also on sheet 23
BL_CTRL: R433.1 R600.1 ; also on sheet 10
COM1_CTS0-: J5.B7(C1_CTS) ; also on sheet 24
COM1_DCD0-: J5.A9(C1_DCD) ; also on sheet 24
COM1_DSR0-: J5.B9(C1_DSR) ; also on sheet 24
COM1_DTR0-: J5.A6(C1_DTR) ; also on sheet 24
COM1_RTS0-: J5.B8(C1_RTS) ; also on sheet 24
COM1_RX0: J5.A7(C1_TXD) ; also on sheet 24
COM1_TX0: J5.A8(C1_RXD) ; also on sheet 24
COM2_CTS_R: J5.B2(C2_CTS) ; also on sheet 24
COM2_DCD_R: J5.A4(C2_DCD) ; also on sheet 24
COM2_DSR_R: J5.B4(C2_DSR) ; also on sheet 24
COM2_DTR_R: J5.A1(C2_DTR) ; also on sheet 24
COM2_RS232_RX: J5.A2(C2_TXD) ; also on sheet 24
COM2_RS232_TX: J5.A3(C2_RXD) ; also on sheet 24
COM2_RTS_R: J5.B3(C2_RTS) ; also on sheet 24
COM4_CTS#: J6.E9(C4_CTS) ; also on sheet 22
COM4_DCD#: J6.D11(C4_DCD) ; also on sheet 22
COM4_DSR#: J6.E11(C4_DSR) ; also on sheet 22
COM4_DTR#: J6.D8(C4_DTR) ; also on sheet 22
COM4_RI#: J6.E8(C4_RI) ; also on sheet 22
COM4_RTS#: J6.E10(C4_RTS) ; also on sheet 22
COM4_RX: J6.D10(C4_RXD) ; also on sheet 22
COM4_TX: J6.D9(C4_TXD) ; also on sheet 22
CRT_BLU_RIO: C472.1 FB46.1 R420.2 ; also on sheet 26
CRT_GRN_RIO: C470.1 FB47.1 R444.2 ; also on sheet 26
CRT_HSYNC_RIO: C649.1 D25.3 J6.E2(VGA_HSYNC) ; also on sheet 26
CRT_RED_RIO: C560.1 FB45.1 R449.2 ; also on sheet 26
CRT_VSYNC_RIO: C650.1 D21.3 J6.D2(VGA_VSYNC) ; also on sheet 26
DDC_CLK_RIO: C651.1 J6.D1(VGA_DDC_CLK) ; also on sheet 26
DDC_DAT_RIO: C652.1 J6.E1(VGA_DDC_DAT) ; also on sheet 26
DDR2_VCC: PC32.2 PC36.1 PR6.2 PR7.2 PR14.1 PU2.8(COMP) PU2.14(V5IN)
DH_1.8: PQ15.4(G) PR9.2
DMG_SELF: J5.D11(HD_DAMAGE_SELF) ; also on sheet 24
DPRSLPVR1: R513.2 R520.1 U29.45(DPRSLPVR)
DVI_A_CLK: J6.A4(DVI_TXC+) ; also on sheet 35
DVI_A_CLK#: J6.B4(DVI_TXC-) ; also on sheet 35
DVI_A_HPD: R453.2 ; also on sheet 35
DVI_A_TX0: J6.A1(DVI_TX0+) ; also on sheet 35
DVI_A_TX0#: J6.B1(DVI_TX0-) ; also on sheet 35
DVI_A_TX1: J6.A2(DVI_TX1+) ; also on sheet 35
DVI_A_TX1#: J6.B2(DVI_TX1-) ; also on sheet 35
DVI_A_TX2: J6.A3(DVI_TX2+) ; also on sheet 35
DVI_A_TX2#: J6.B3(DVI_TX2-) ; also on sheet 35
HDDLED#: D19.3(A) LED3.3 Q18.1(GATE) R693.1 U79.4(OUT)
HWPG_DDR: PR8.1 PU2.13(PGOOD)
ICH_DPRSTP#: R515.1 ; also on sheet 15
IDELED#: D19.1(C1) R699.2 U79.2(INA) ; also on sheet 24
ISEN1: C487.2 R518.1 U29.24(ISEN1)
ISEN2: C499.2 R538.1 U29.23(ISEN2)
J5_COM3_DCD#: J6.D16(C3_DCD) ; also on sheet 22
J5_COM3_DSR#: J6.E16(C3_DSR) ; also on sheet 22
J5_COM3_DTR#: J6.D13(C3_DTR) ; also on sheet 22
J5_COM3_RI#: J6.E13(C3_RI) ; also on sheet 22
J5_COM3_RTS#: J6.E15(C3_RTS) ; also on sheet 22
J5_COM3_RX: J6.D15(C3_RXD) ; also on sheet 22
J5_COM3_TX: J6.D14(C3_TXD) ; also on sheet 22
J5COM3_CTS#: J6.E14(C3_CTS) ; also on sheet 22
KBCK: CN3.3(C21) FB28.2 J6.A21(KB_CLK)
KBCLK: FB28.1 RN40.7(R4) ; also on sheet 21
KBD: CN3.1(C11) FB29.2 J6.A20(KB_DATA)
KBDATA: FB29.1 RN40.8(R2) ; also on sheet 21
LCDVCC: R114.1 ; also on sheet 25
LINE_L: J5.E16(LINE_IN_L) ; also on sheet 23
LINE_R: J5.E17(LINE_IN_R) ; also on sheet 23
LVDS_TXL0+: J6.B12(LVDS1_TX0+) ; also on sheet 10
LVDS_TXL0-: J6.A12(LVDS1_TX0-) ; also on sheet 10
LVDS_TXL0N: J6.A17(LVDS2_TX0-) ; also on sheet 10
LVDS_TXL0P: J6.B17(LVDS2_TX0+) ; also on sheet 10
LVDS_TXL1+: J6.B11(LVDS1_TX1+) ; also on sheet 10
LVDS_TXL1-: J6.A11(LVDS1_TX1-) ; also on sheet 10
LVDS_TXL1N: J6.A16(LVDS2_TX1-) ; also on sheet 10
LVDS_TXL1P: J6.B16(LVDS2_TX1+) ; also on sheet 10
LVDS_TXL2+: J6.B10(LVDS1_TX2+) ; also on sheet 10
LVDS_TXL2-: J6.A10(LVDS1_TX2-) ; also on sheet 10
LVDS_TXL2N: J6.A15(LVDS2_TX2-) ; also on sheet 10
LVDS_TXL2P: J6.B15(LVDS2_TX2+) ; also on sheet 10
LVDS_TXL3+: J6.B8(LVDS1_TX3+) ; also on sheet 9
LVDS_TXL3-: J6.A8(LVDS1_TX3-) ; also on sheet 9
LVDS_TXL3N: J6.A13(LVDS2_TX3-) ; also on sheet 9
LVDS_TXL3P: J6.B13(LVDS2_TX3+) ; also on sheet 9
LVDS_TXLCK+: J6.B9(LVDS1_CK+) ; also on sheet 10
LVDS_TXLCK-: J6.A9(LVDS1_CK-) ; also on sheet 10
LVDS_TXLCKN: J6.A14(LVDS2_CK-) ; also on sheet 10
LVDS_TXLCKP: J6.B14(LVDS2_CK+) ; also on sheet 10
MCH_DPRSTP#: R515.2 R523.1 U29.46(DPRSTP#) ; also on sheet 9
MIC_IN: J5.E15(MIC_IN) ; also on sheet 23
MPWROK: R380.2 R382.1 R551.2 U37.1(INB) U37.2(INA) ; also on sheet 9 17
MSCK: CN3.5(C31) FB27.2 J6.B21(MS_CLK)
MSCLK: FB27.1 RN40.6(R6) ; also on sheet 21
MSD: CN3.7(C41) FB26.2 J6.B20(MS_DATA)
MSDATA: FB26.1 RN40.5(R8) ; also on sheet 21
PM_DPRSLPVR: R513.1 ; also on sheet 9 17
PS_ON#: R345.2 ; also on sheet 21
PSI#: R510.1 ; also on sheet 5
PSI#1: R510.2 R519.2 U29.2(PSI#)
PWRBTN: R364.2 ; also on sheet 17 21 25
PWROK: R382.2 R572.2 U37.4(OUT) ; also on sheet 9 17 21 26
R_USBP0+: J5.E2(USB0+) RN35.3(R21)
R_USBP0-: J5.E3(USB0-) RN35.1(R11)
R_USBP1+: J5.D2(USB1+) RN35.7(R41)
R_USBP1-: J5.D3(USB1-) RN35.5(R31)
R_USBP2+: J5.E7(USB2+) RN33.3(R21)
R_USBP2-: J5.E8(USB2-) RN33.1(R11)
R_USBP3+: J5.D7(USB3+) RN33.7(R41)
R_USBP3-: J5.D8(USB3-) RN33.5(R31)
REAR_CRT_B: C562.1 D23.3 FB48.2 J6.D3(VGA_BLUE)
REAR_CRT_G: C561.1 D22.3 FB49.2 J6.E3(VGA_GREEN)
REAR_CRT_R: C563.1 D24.3 FB50.2 J6.D4(VGA_RED)
RINGW0: J5.B6(C1_RI) ; also on sheet 24
RINGW1_R: J5.B1(C2_RI) ; also on sheet 24
RSV1: J5.A5(RSV1)
RSV2: J5.A10(RSV2)
RSV5: J5.A24(RSV5)
RSV14: J5.C1(RSV14)
RSV20: J6.C16(RSV20)
RSV21: J6.C17(RSV21)
RSV26: J5.C16(RSV26)
RSV49: J5.E20(RSV49)
S4_STATE#: PR10.2 R631.1 ; also on sheet 17
SATA_RX1C+: J5.A19(SATA1_RX+) ; also on sheet 15
SATA_RX1C-: J5.A20(SATA1_RX-) ; also on sheet 15
SATA_RX3C+: J5.B19(SATA2_RX+) ; also on sheet 15
SATA_RX3C-: J5.B20(SATA2_RX-) ; also on sheet 15
SATA_TX1C+: J5.A16(SATA1_TX+) ; also on sheet 15
SATA_TX1C-: J5.A17(SATA1_TX-) ; also on sheet 15
SATA_TX3C+: J5.B16(SATA2_TX+) ; also on sheet 15
SATA_TX3C-: J5.B17(SATA2_TX-) ; also on sheet 15
SATALED#: D19.2(C2) U79.1(INB) ; also on sheet 15
SCLDDC: J6.B5(DVI_DDC_CLK) ; also on sheet 35
SDADDC: J6.A5(DVI_DDC_DAT) ; also on sheet 35
SLP_S3#: R629.1 U38.1(INB) U38.2(INA) U40.1(INB) U40.2(INA) ; also on sheet 17 21 34
SMDDR_VREF: PC41.1 PU2.7(VTTREF) ; also on sheet 9 14 38
SMDDR_VTERM: C529.1 C530.1 C531.1 C532.1 PU2.2(VTT) PU2.4(VTTSNS) R441.1 ; also on sheet 14 37
SYS_RST_FP: J5.A11(SYSTEM_RST#) ; also on sheet 25
USBP0N: RN35.2(R12) ; also on sheet 16
USBP0P: RN35.4(R22) ; also on sheet 16
USBP1N: RN35.6(R32) ; also on sheet 16
USBP1P: RN35.8(R42) ; also on sheet 16
USBP2N: RN33.2(R12) ; also on sheet 16
USBP2P: RN33.4(R22) ; also on sheet 16
USBP3N: RN33.6(R32) ; also on sheet 16
USBP3P: RN33.8(R42) ; also on sheet 16
VCORE_LG0: PQ19.4(G) U29.32(LGATE1)
VCORE_LG1: PQ8.4(G) U29.30(LGATE2)
VCORE_PH0: PC7.1 PD2.2(C) PL1.1 PQ18.1(S1) PQ18.2(S2) PQ18.3(S3) PQ19.5(D) R509.1 R518.2 R521.2 U29.34(PHASE1)
VCORE_PH1: C485.1 PD3.2(C) PL2.1 PQ7.1(S1) PQ7.2(S2) PQ7.3(S3) PQ8.5(D) R533.1 R537.2 R538.2 U29.28(PHASE2)
VCORE_UG0: PQ18.4(G) U29.35(UGATE1)
VCORE_UG1: PQ7.4(G) U29.27(UGATE2)
VID0: RN41.5(R31) U29.37(VID0) ; also on sheet 6
VID1: RN41.3(R21) U29.38(VID1) ; also on sheet 6
VID2: RN41.1(R11) U29.39(VID2) ; also on sheet 6
VID3: RN42.7(R41) U29.40(VID3) ; also on sheet 6
VID4: RN42.5(R31) U29.41(VID4) ; also on sheet 6
VID5: RN42.3(R21) U29.42(VID5) ; also on sheet 6
VID6: RN42.1(R11) U29.43(VID6) ; also on sheet 6
VR_ON1: R512.2 U29.44(VR_ON)
VR_PWRGD: R511.2 R547.2 R550.2 ; also on sheet 17
VR_PWRGD_R: C566.2 R508.2 R511.1 U26.2(VCC)
VRIN0: C398.2 C399.2 L10.1 PC8.1 PC19.1 PQ7.5(D) PQ18.5(D)
VSUM: C493.2 C494.2 R509.2 R531.1 R533.2 R534.2 U29.19(VSUM)
N8241773: PR11.2 U38.4(OUT)
N8241915: PC36.2 PR7.1 PU2.15(CS)
N8242139: PR11.1 PU2.11(S3)
N47586677: PR10.1 PU2.12(S5)
N63569583: C486.2 R524.1 U29.9(VW)
N63569597: R514.1 U29.36(BOOT1)
N63569615: PC6.2 R503.2 U29.20(VIN)
N63569664: C501.1 U29.7(SOFT)
N63569676: PC4.2 R505.2 U29.48(3V3)
N63569678: C486.1 C490.2 R524.2 R525.2 U29.10(COMP)
N63569692: C488.1 C490.1 R526.2 R527.2 U29.11(FB)
N63569727: C483.1 R504.2 U29.22(VDD)
N63569839: C497.2 R540.1 U29.8(OCSET)
N63569887: R529.1 R531.2
N63569985: R545.2 R546.1 U29.17(DFB)
N63570007: C498.1 R537.1
N63570011: C502.1 R545.1 U29.16(DROOP)
N63570016: C484.2 R506.2 U29.31(PVCC)
N63570088: C491.2 R526.1 U29.13(VDIFF)
N63570103: R535.2 U29.15(RTN)
N63570164: R532.2 U29.14(VSEN)
N63570178: C491.1 R527.1
N63570195: R507.1 R508.1 U29.1(PGOOD)
N63570287: PC7.2 R514.2
N63570319: C489.1 R521.1
N63570321: R544.1 U29.4(RBIAS)
N63570402: R541.2 U29.5(VR_TT#)
N63570404: C485.2 R517.2
N63571010: R517.1 U29.26(BOOT2)
N65053458: C504.2 R547.1 U30.1(INB) U30.2(INA)
N78097063: PQ11.1(B) R601.2
N88591637: R542.2 U29.6(NTC)
N88951834: C488.2 R525.1
N98259479: C519.2 R563.1 U33.5(VCC)
N98259481: C513.1 C515.2 C520.1 R565.1 R569.1 U33.6(FB)
N98259483: C514.2 PD5.2(C) U33.1(BOOT)
N98259510: C516.1 R568.1
N98259521: C513.2 R564.2
N98259561: R569.2 R570.1 R571.1
N98259588: C520.2 R571.2
N98310123: C445.2 Q92.1(C) Q92.2(R) R373.2 R374.1
N98334924: C348.2 R374.2 R375.1 U39.3(-)
N98392743: PQ20.4(G) R606.1 U39.1(O)
N98520891: PQ28.3(G) R607.1 U39.7(O)
N98520909: C349.2 PR488.1 R431.1 U39.5(-)
N98580579: PQ27.3(DRAIN) Q22.1(GATE) R608.1
N98580588: R609.1 U40.4(OUT)
N98580661: PQ27.1(GATE) R609.2
N104419299: R380.1 U30.4(OUT)
N104424146: R550.1 U26.1(~{RST})
N109930553: Q15.1(B) R629.2
N109950874: Q15.3(C) Q25.1(GATE) Q26.1(GATE) Q27.1(GATE) Q28.1(GATE) Q31.1(GATE) Q32.1(GATE) R630.1
N109953785: Q25.3(DRAIN) R435.2
N109956698: Q26.3(DRAIN) R437.2
N109959613: Q27.3(DRAIN) R438.2
N109962530: Q28.3(DRAIN) R440.2
N110016397: Q17.3(C) Q29.1(GATE) Q30.1(GATE) R632.1
N110016510: Q29.3(DRAIN) R446.2
N110016540: Q17.1(B) R631.2
N110016546: Q30.3(DRAIN) R441.2
N110034368: Q31.3(DRAIN) R443.2
N110034376: Q32.3(DRAIN) R445.2
N114210839: F2.2 FB6.1
N114222599: F3.2 FB8.1
N114226453: F4.2 FB15.1
N114230319: F5.2 FB19.1
N114525128: J6.A6(DVI_HPD) R453.1
N114727384: J6.E19(POWER_LED) R697.1
N115570188: C467.1 FB45.2 FB50.1
N115570190: C471.1 FB47.2 FB49.1
N115570200: C462.1 FB46.2 FB48.1
N116884486: J6.E21(HDD_LED) Q18.3(DRAIN) R700.1
N119738051: J6.D17(RSV39) R105.2
N119746300: J6.E17(RSV57) R345.1
N119755153: J6.E18(RSV58) R364.1
N120017077: R542.1 R543.1
N123926701: J6.B18(RSV4) R114.2
N123937762: J6.A18(RSV2) R433.2
N124432123: LED3.4 R695.1
N124449975: LED3.2 R696.1

Not connected (* = marked no-connect by the designer): J5 A22(RSV3)* A23(RSV4)* A25(RSV6)* B5(RSV7)* B10(RSV8)* B11(RSV9)* B22(RSV10)* B23(RSV11)* B24(RSV12)* B25(RSV13)* C2(RSV15)* C3(RSV16)* C4(RSV17)* C5(RSV18)* C6(RSV19)* C7(RSV20)* C8(RSV21)* C9(RSV22)* C10(RSV23)* C11(RSV24)* C15(RSV25)* C17(RSV27)* C18(RSV28)* C19(RSV29)* C20(RSV30)* C21(RSV31)* C22(RSV32)* C23(RSV33)* C24(RSV34)* C25(RSV35)* D5(RSV36)* D10(RSV37)* D17(RSV38)* D19(RSV39)* D20(RSV40)* D21(RSV41)* D22(RSV42)* D23(RSV43)* D24(RSV44)* D25(RSV45)* E5(RSV46)* E10(RSV47)* E11(RSV48)* E21(RSV50)* E22(RSV51)* E23(RSV52)* E24(RSV53)* E25(RSV54)* F3(GND3) F4(GND4) F5(GND5) F6(GND6) F7(GND7) F8(GND8) F9(GND9) F10(GND10) F11(GND11) F12(GND13) F13(GND14) F14(GND12) F15(GND15) F16(GND16) F17(GND17) F18(GND18) F19(GND19) F20(GND20) F21(GND21) F22(GND22) F23(GND23) F24(GND24) F25(GND25); J6 A7(RSV1)* B7(RSV3)* C1(RSV5)* C2(RSV6)* C3(RSV7)* C4(RSV8)* C5(RSV9)* C6(RSV10)* C7(RSV11)* C8(RSV12)* C9(RSV13)* C10(RSV14)* C11(RSV15)* C12(RSV16)* C13(RSV17)* C14(RSV18)* C15(RSV19)* C18(RSV22)* C19(RSV23)* C20(RSV24)* C21(RSV25)* C22(RSV26)* D5(RSV27)* D6(RSV28)* D7(RSV29)* D12(RSV34)* D18(RSV40) D19(RSV41) D20(RSV42) D21(RSV43) D22(RSV44) E5(RSV45)* E6(RSV46)* E7(RSV47)* E12(RSV52)*; RN41 7(R41)*; U29 3(PGD_IN)* 12(FB2)* 25(NC)* 47(CLK_EN#)*

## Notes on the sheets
sheet 30
- Place close to CPCI J5
- ?
- Place close to CPCI J5
- ?
- PCB Top View:
- Front View:
- 3
- 1
- (Green)
- Power
- 4
- 2
- (Yellow/Blue)
- HDD/Hot swap
- 2+,1- => yellow
- 2-,1+ => blue
- 4+,3- => Green
- (ªOÃä)
- Place close to CPCI J5
- (SH-31G(YB)-2)
sheet 31
- 0.7~1.708V/41A
sheet 32
- Discharge Circuit
sheet 33
- Current Limit=8.6A
- 8.0A
- +0.9V
- 1.5A
- OCP SETS AT 16A.
- Vout=Vref*(1+R1/R2)=0.8*(1+2.2K/2.49K)=1.507
- Ipeak=16A=Iocset*Rset/Rdson=20*10/12.5=16A
